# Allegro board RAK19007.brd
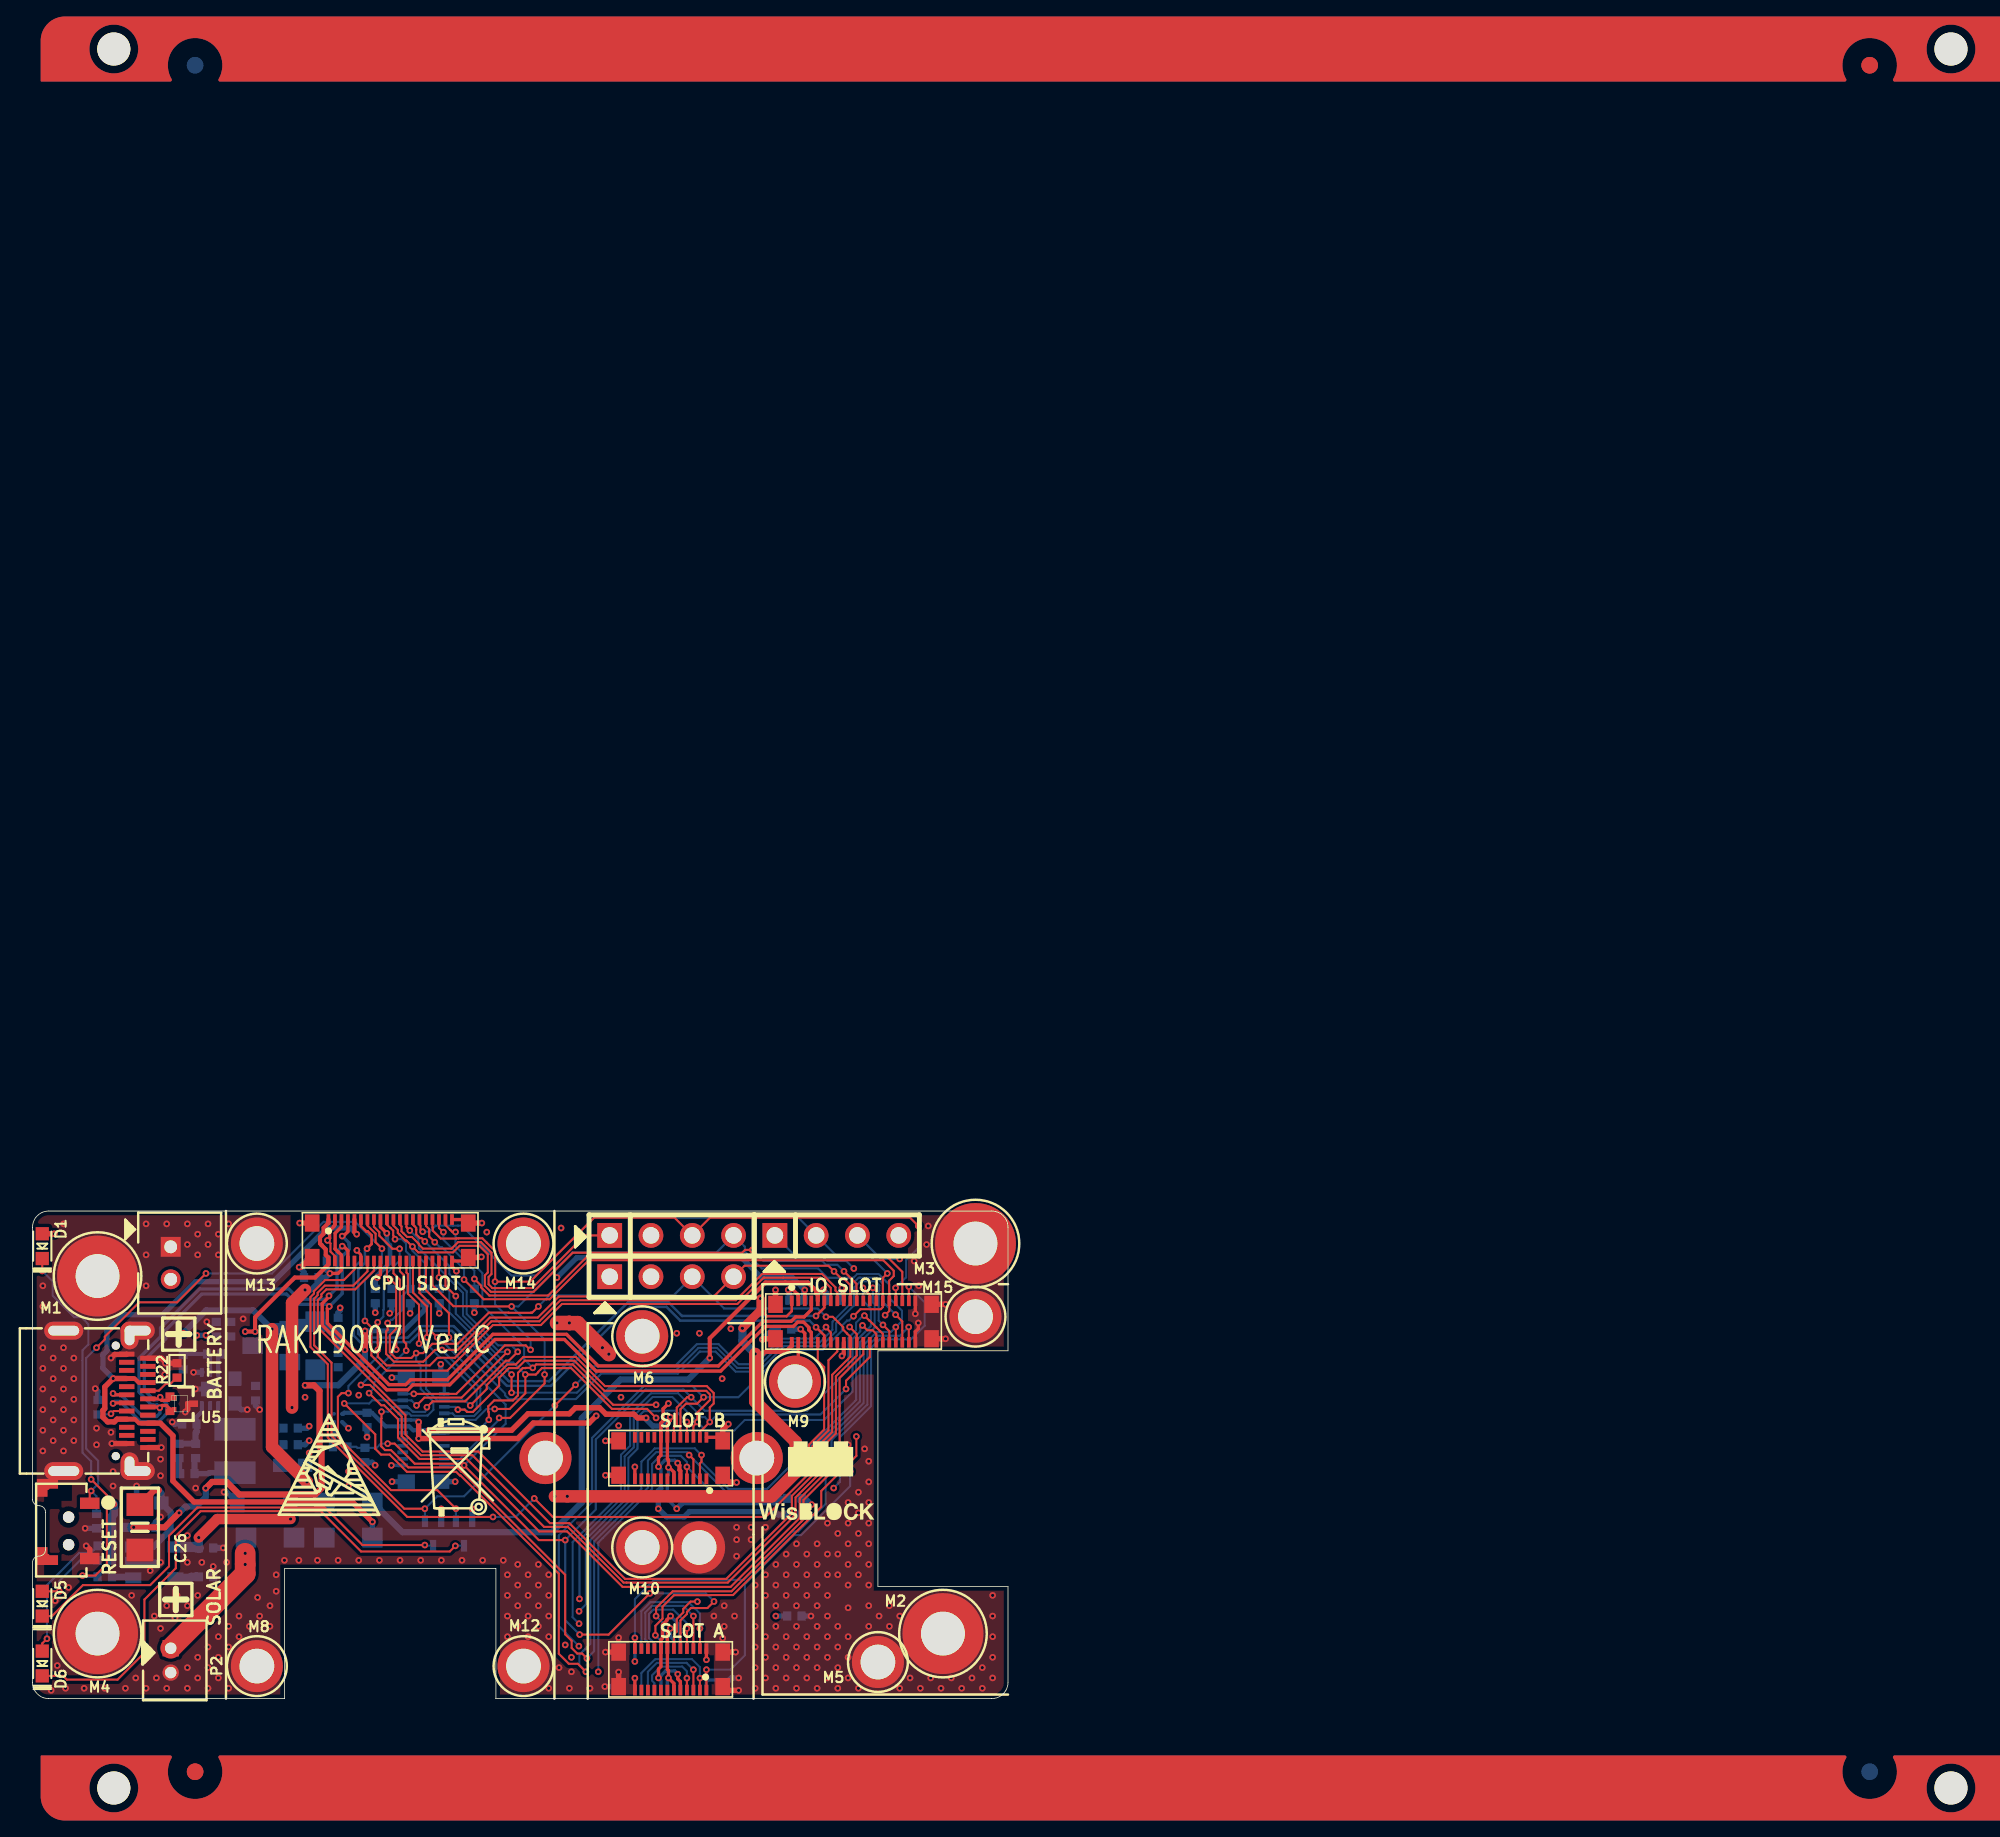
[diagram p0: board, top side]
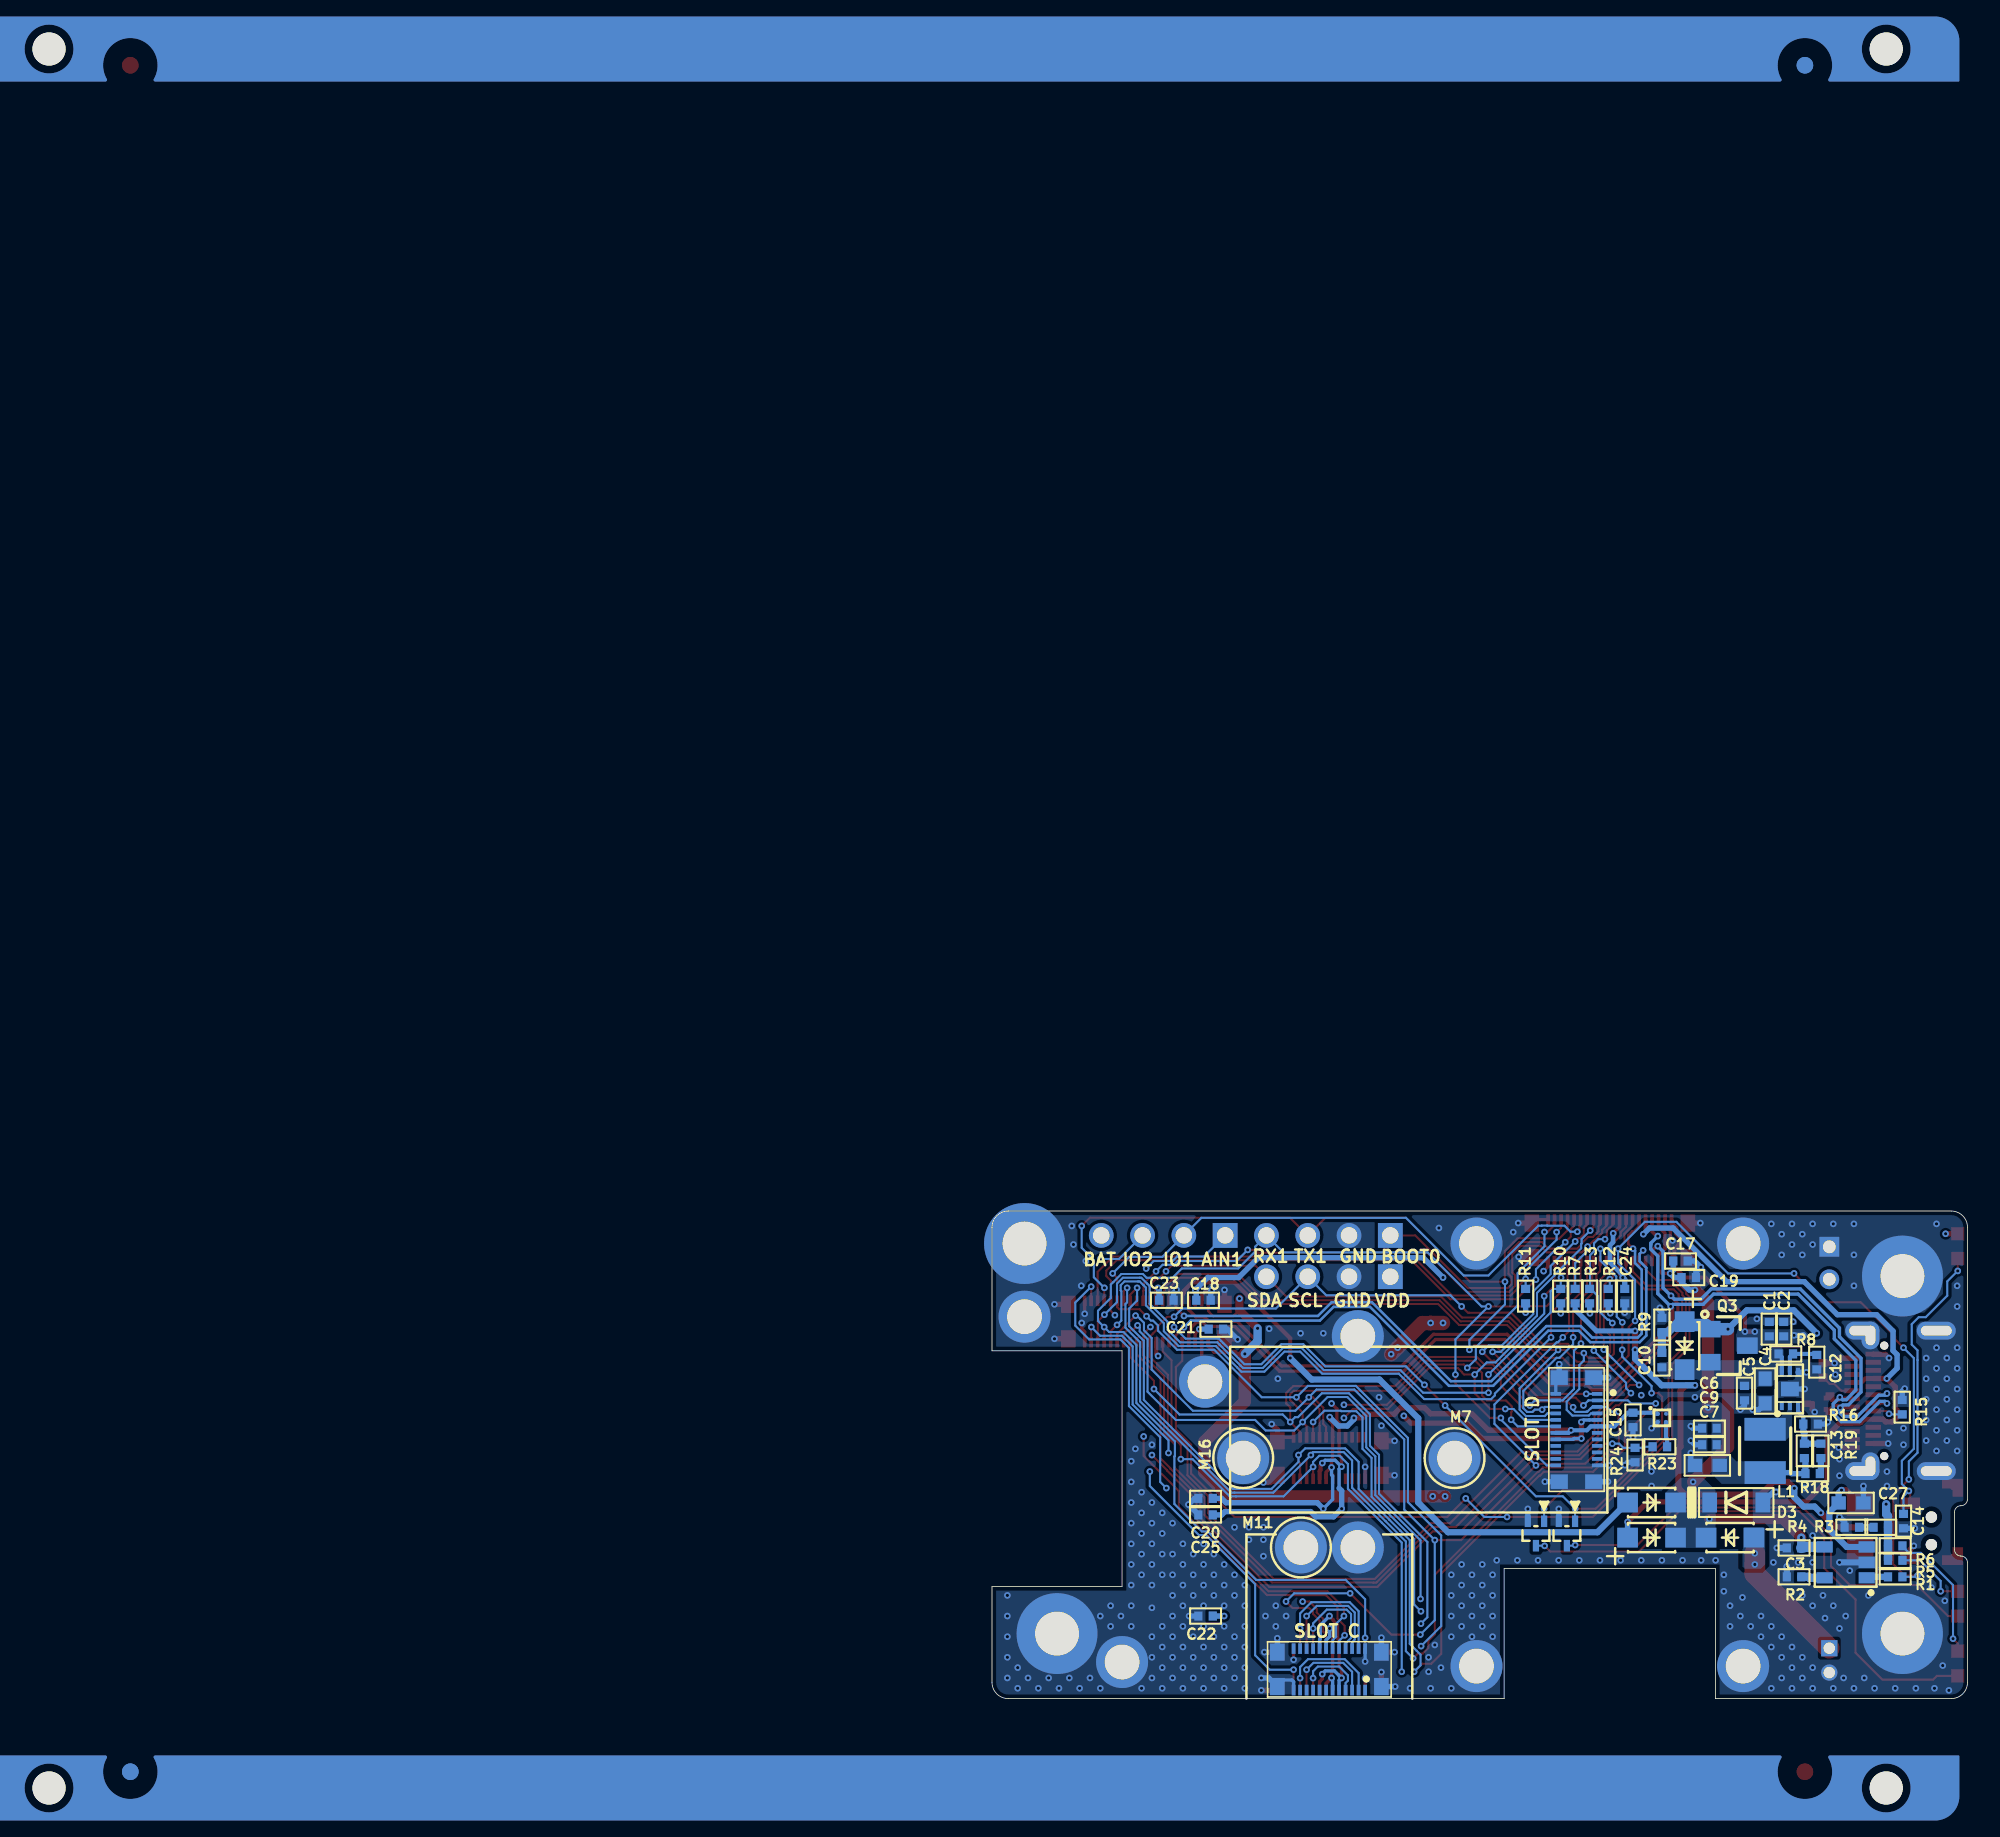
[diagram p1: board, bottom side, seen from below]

Outline 60 x 30 mm; copper layers: TOP, GND, POWER, BOTTOM. Coordinates in mm from the lower left corner of the outline.
Outline path: 0,29 0,12.27 arc(0.12,11.99) 0.4,11.87 arc(0.68,11.75) 0.8,11.47 0.8,9.17 arc(0.68,8.89) 0.4,8.77 arc(0.12,8.65) 0,8.37 0,1 arc(0.29,0.29) 1,0 15.5,0 15.5,8 28.5,8 28.5,0 59,0 arc(59.71,0.29) 60,1 60,6.9 52,6.9 52,21.4 60,21.4 60,29 arc(59.71,29.71) 59,30 1,30 arc(0.29,29.71) 0,29

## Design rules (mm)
constraint set DEFAULT: min track width 0.127
net group DIFFPAIR0: nets RXD0 TXD0
net group DIFFPAIR2: nets USB+ USB-
net group POWER: nets 3V3_S VBUS
net group DEFAULT: nets ADC_VBAT AIN0 AIN1 BOOT0 I2C1_SCL I2C1_SDA I2C2_SCL I2C2_SDA IO1 IO2 IO3 IO4 IO5 IO6 IO8 LED1 LED2 N577502 N581567 N582068 N712650 N5338470 N5774440 N5815470 RESET RXD1 SPI_CLK SPI_CS SPI_MISO SPI_MOSI SW1 TXD1

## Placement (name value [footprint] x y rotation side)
C1  10uF  [SC0402]  12.19 22.73 270 bottom
C2  100nF  [SC0402]  11.3 22.73 270 bottom
C3  1uF  [SC0402]  10.67 9.27 180 bottom
C4  22uF  [SC0603]  12.45 18.92 90 bottom
C5  100nF  [SC0402]  13.72 18.8 90 bottom
C6  10pF  [SC0402]  15.88 16.64 180 bottom
C7  22uF  [SC0603]  16 14.35 180 bottom
C9  100nF  [SC0402]  15.88 15.62 180 bottom
C10  100nF  [SC0402]  18.8 20.83 270 bottom
C12  100nF  [SC0402]  9.27 20.7 90 bottom
C13  22pF  [SC0402]  10.03 15.24 270 bottom
C14  100nF  [SC0402]  3.94 10.92 90 bottom
C15  100nF  [SC0402]  20.57 17.14 90 bottom
C17  10uF  [SC0402]  17.65 26.92 0 bottom
C18  10pF  [SC0402]  46.99 24.51 0 bottom
C19  100nF  [SC0402]  17.14 25.91 0 bottom
C20  10uF  [SC0402]  46.86 12.32 180 bottom
C21  10pF  [SC0402]  46.23 22.73 0 bottom
C22  100nF  [SC0402]  46.86 5.08 180 bottom
C23  10uF  [SC0402]  49.28 24.51 0 bottom
C24  10pF  [SC0402]  21.08 24.77 90 bottom
C25  100nF  [SC0402]  46.86 11.3 180 bottom
C26  100uF  [SC1206]  6.6 10.54 90 top
C27  22uF/NC  [SC0603]  7.16 12.04 0 bottom
D1  RED  [SD0603-LED-B]  0.6 27.84 270 top
D2  MBR140SFT1G  [MBR140SF]  19.43 9.91 180 bottom
D3  LBZT52B5V6T1G  [SOD-123]  14.22 12.06 180 bottom
D4  MBR140SFT1G  [MBR140SF]  14.61 9.91 0 bottom
D5  GREEN  [SD0603-LED-B]  0.6 5.84 270 top
D6  BLUE  [SD0603-LED-B]  0.6 2.16 270 top
D7  MBR140SFT1G  [MBR140SF]  19.43 12.06 180 bottom
D8  MBR140SFT1G  [MBR140SF]  17.4 21.72 270 bottom
J1  Type-C  [USB-C-04-24P]  5.12 14.92 270 top
J3  12VDC  [TSW4-RG_1]  2.22 10.32 270 top
J4  BTB24_F  [BTB24_2X20_4MM_F]  39.25 1.8 270 top
J5  BTB40_F  [BTB40_2X20_4MM_F]  22 28.2 90 top
J6  BTB24_F  [BTB24_2X20_4MM_F]  39.25 14.8 270 top
J7  BTB40_F  [BTB40_2X20_4MM_F]  50.5 23.2 90 top
J8  BTB24_F  [BTB24_2X20_4MM_F]  39.25 1.8 270 bottom
J9  BTB24_F  [BTB24_2X20_4MM_F]  24.05 16.55 180 bottom
J10  NC  [PH254-115-04]  39.31 28.5 90 top
J11  NC  [PH254-115-04]  49.47 28.5 90 top
J12  NC  [PH254-115-04]  39.31 25.96 90 top
L1  4.7uH  [SL1008]  12.45 15.24 270 bottom
M1  NC  [PH106-196]  4 26 0 top
M2  NC  [PH106-196]  56 4 0 top
M3  NC  [PH106-196]  58 28 0 top
M4  NC  [PH106-196]  4 4 0 top
M5  DNP  [PH84-126]  52 2.25 0 top
M6  DNP  [PH84-126]  37.5 22.3 0 top
M7  DNP  [PH84-126]  31.55 14.8 180 bottom
M8  DNP  [PH84-126]  13.8 2 0 top
M9  DNP  [PH84-126]  46.9 19.5 0 top
M10  DNP  [PH84-126]  37.5 9.3 0 top
M11  DNP  [PH84-126]  41 9.3 180 bottom
M12  DNP  [PH84-126]  30.2 2 0 top
M13  DNP  [PH84-126]  13.8 28 0 top
M14  DNP  [PH84-126]  30.2 28 0 top
M15  DNP  [PH84-126]  58 23.5 0 top
M16  DNP  [PH84-126]  44.55 14.8 180 bottom
NOREF  -  []  8.89 18.8 0 top
NOREF#2  -  []  28.7 14.35 0 top
NOREF#3  -  [unnamed#2]  0 -3 0 top
NOREF#4  -  [unnamed#2]  123 99 180 top
NOREF#5  -  []  158.12 -65.91 0 top
NOREF#6  -  []  47.75 13.21 0 top
NOREF#7  -  [unnamed#2]  123 -3 180 bottom
NOREF#8  -  [unnamed#2]  0 99 0 bottom
P1  BATT_CONN  [PH2MM_2A]  8.5 26.8 0 top
P2  Solar, Wireless charger and Wind Power input connector  [PH150-2P]  8.5 2.35 0 top
Q1  DTC043ZEBTL  [SOT-416]  24.64 10.16 0 bottom
Q2  DTC043ZEBTL  [SOT-416]  26.54 10.16 0 bottom
Q3  NCE40P05Y  [SOT23]  14.68 21.72 270 bottom
R1  1K  [SR0402]  4.45 7.49 0 bottom
R2  2.7K  [SR0402]  10.67 7.49 0 bottom
R3  1M  [SR0402]  5.33 10.54 0 bottom
R4  1.5M  [SR0402]  7.11 10.54 0 bottom
R5  4.7K  [SR0402]  4.45 8.51 0 bottom
R6  4.7K  [SR0402]  4.45 9.4 0 bottom
R7  0  [SR0402]  24.13 24.77 90 bottom
R8  4.7K  [SR0402]  11.18 21.21 180 bottom
R9  4.7K  [SR0402]  18.8 22.99 270 bottom
R10  4.7K  [SR0402]  25.02 24.77 270 bottom
R11  4.7K  [SR0402]  27.18 24.77 270 bottom
R12  4.7K  [SR0402]  22.1 24.77 270 bottom
R13  4.7K  [SR0402]  23.24 24.77 270 bottom
R15  4.7K  [SR0402]  4.01 17.93 90 bottom
R16  1M  [SR0402]  9.65 16.89 0 bottom
R18  1.5M  [SR0402]  9.53 13.84 0 bottom
R19  800K  [SR0402]  9.02 15.24 270 bottom
R22  4.7K  [SR0402]  8.89 20.19 90 top
R23  10K  [SR0402]  18.92 15.49 180 bottom
R24  100k/NC  [SR0402]  20.45 14.99 270 bottom
U2  TP4054  [SOT-23-5]  6.2 8.38 90 bottom
U3  SGM6036-ADJ  [UTDFN-1_5X2-6L]  10.92 19.05 90 bottom
U4  TPD2EUSB30DRTR/NC  [3PSOT41X33F]  8.7 18.49 270 top
U5  PPJE5V0U8TB-AU  [SOT-523]  9.18 18.14 270 top
U6  SGM2578AADYG/TR  [DSBGA_0_9X0_9MM]  18.8 17.27 180 bottom

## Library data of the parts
C1-C7 C9 C10 C12-C15 C17-C27 = CAPACITOR NP
D1 D5 D6 = LED
D2 D4 D7 D8 = DIODE_SCHOTTKY
D3 = DIODE_ZENER_INV
J1 = CONN_USB3_0
J3 = BUTTON_1
J4 J6 J8 J9 = BTB24_2X12_0
J5 J7 = BTB40_2x20_4mm
J10-J12 = HEADER1X4: User Part Number: PH254-115-04
L1 = INDUCTOR _POWER
M1-M16 = HOLE
P1 = HEADER2: User Part Number: NC
P2 = HEADER2_150
Q1 Q2 = TRIODE_NPN_RES
Q3 = MOSFET_P_DIODE_3P
R1-R13 R15 R16 R18 R19 R22-R24 = RESISTOR
U2 = TP4054
U3 = SGM6036-ADJ
U4 = TPD2EUSB30DRTR: User Part Number: PART
U5 = TVS_3PIN
U6 = TPS22908

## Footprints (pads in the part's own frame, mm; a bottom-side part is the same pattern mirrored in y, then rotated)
3PSOT41X33F
  rect 0.3x0.3 smd: 1(0,0) 2(0.7,0) 3(0.35,0.85)
BTB24_2X20_4MM_F
  rect 0.65x0.23 smd: 1(1.275,2.2) 2(-1.275,2.2) 3(1.275,1.8) 4(-1.275,1.8) 5(1.275,1.4) 6(-1.275,1.4) 7(1.275,1) 8(-1.275,1) 9(1.275,0.6) 10(-1.275,0.6) 11(1.275,0.2) 12(-1.275,0.2) 13(1.275,-0.2) 14(-1.275,-0.2) 15(1.275,-0.6) 16(-1.275,-0.6) 17(1.275,-1) 18(-1.275,-1) 19(1.275,-1.4) 20(-1.275,-1.4) 21(1.275,-1.8) 22(-1.275,-1.8) 23(1.275,-2.2) 24(-1.275,-2.2)
  rect 1.06x0.9 smd: F1(-1.06,3.2) F2(1.06,3.2) F3(-1.06,-3.2) F4(1.06,-3.2)
BTB40_2X20_4MM_F
  rect 0.65x0.23 smd: 1(1.275,3.8) 2(-1.275,3.8) 3(1.275,3.4) 4(-1.275,3.4) 5(1.275,3) 6(-1.275,3) 7(1.275,2.6) 8(-1.275,2.6) 9(1.275,2.2) 10(-1.275,2.2) 11(1.275,1.8) 12(-1.275,1.8) 13(1.275,1.4) 14(-1.275,1.4) 15(1.275,1) 16(-1.275,1) 17(1.275,0.6) 18(-1.275,0.6) 19(1.275,0.2) 20(-1.275,0.2) 21(1.275,-0.2) 22(-1.275,-0.2) 23(1.275,-0.6) 24(-1.275,-0.6) 25(1.275,-1) 26(-1.275,-1) 27(1.275,-1.4) 28(-1.275,-1.4) 29(1.275,-1.8) 30(-1.275,-1.8) 31(1.275,-2.2) 32(-1.275,-2.2) 33(1.275,-2.6) 34(-1.275,-2.6) 35(1.275,-3) 36(-1.275,-3) 37(1.275,-3.4) 38(-1.275,-3.4) 39(1.275,-3.8) 40(-1.275,-3.8)
  rect 1.06x0.9 smd: F1(-1.06,4.8) F2(1.06,4.8) F3(-1.06,-4.8) F4(1.06,-4.8)
DSBGA_0_9X0_9MM
  round 0.23 smd: A1(-0.25,0.25) A2(0.25,0.25) B1(-0.25,-0.25) B2(0.25,-0.25)
MBR140SF
  rect 1.27x1.219 smd: 1(-1.475,0) 2(1.475,0)
PH2MM_2A
  rect 1.219x1.219 hole 0.787: 1(0,1)
  round 1.219 hole 0.787: 2(0,-1)
PH84-126
  round 3.2 hole 2.134: 1(0,0)
PH106-196
  round 4.978 hole 2.692: 1(0,0)
PH150-2P
  rect 1x1 hole 0.7: 1(0,0.75)
  round 1 hole 0.7: 2(0,-0.75)
PH254-115-04
  rect 1.524x1.524 hole 1.016: 1(0,3.81)
  round 1.524 hole 1.016: 2(0,1.27) 3(0,-1.27) 4(0,-3.81)
SC0402
  rect 0.508x0.559 smd: 1(-0.445,0) 2(0.445,0)
SC0603
  rect 0.889x0.813 smd: 1(-0.762,0) 2(0.762,0)
SC1206
  rect 1.397x1.651 smd: 1(-1.397,0) 2(1.397,0)
SD0603-LED-B
  rect 0.813x0.813 smd: 1(-0.762,0) 2(0.762,0)
SL1008
  rect 1.397x2.54 smd: 1(-1.333,0) 2(1.333,0)
SOD-123
  rect 0.91x1.22 smd: 1(-1.635,0) 2(1.635,0)
SOT23
  rect 1.016x1.27 smd: 1(-1.016,-1.143) 2(1.016,-1.143) 3(0,1.143)
SOT-23-5
  rect 0.69x0.99 smd: 1(-0.95,0)
  rect 0.69x1 smd: 2(0,0) 3(0.95,0) 4(0.95,2.59) 5(-0.95,2.59)
SOT-416
  rect 0.381x0.711 smd: 1(-0.5,-0.75) 2(0.5,-0.75) 3(0,0.75)
SOT-523
  rect 0.4x0.55 smd: 1(-0.5,-0.725) 2(0.5,-0.725) 3(0,0.725)
SR0402
  rect 0.508x0.559 smd: 1(-0.445,0) 2(0.445,0)
TSW4-RG_1
  round 0.7 hole 0.7 unplated: (-0.85,0) (0.85,0)
  rect 0.7x1.2 smd: 1(-1.7,1.3) 2(1.7,1.3)
  custom 0.275x0.275 smd: 3(-2.65,-1.3) 4(1.55,-1.3)
unnamed#2
  round 2.032 hole 2.032 unplated: (5,-2.5)
  round 1.016 smd: (10,-1.5) (10,-1.5)
USB-C-04-24P
  round 0.5 hole 0.5 unplated: (-6.8,0) (0,0)
  oval 1.1x2.4 hole 0.6x1.9: 1(-7.72,-3.201) 2(0.92,-3.201)
  oval 1.1x2.1 hole 0.6x1.6: 3(-7.72,1.349) 4(0.92,1.349)
  oval 1.7x1.1 hole 1.2x0.6: 7(-7.42,0.848) 8(0.62,0.848)
  rect 0.3x0.95 smd: A1(-6.025,1.975) A2(-5.525,1.975) A3(-5.025,1.975) A4(-4.525,1.975) A5(-4.025,1.975) A6(-3.525,1.975) A7(-3.025,1.975) A8(-2.525,1.975) A9(-2.025,1.975) A10(-1.525,1.975) A11(-1.025,1.975) A12(-0.525,1.975) B1(-0.775,0.675) B2(-1.275,0.675) B3(-1.775,0.675) B4(-2.275,0.675) B5(-2.775,0.675) B6(-3.275,0.675) B7(-3.775,0.675) B8(-4.275,0.675) B9(-4.775,0.675) B10(-5.275,0.675) B11(-5.775,0.675) B12(-6.275,0.675)
UTDFN-1_5X2-6L
  rect 0.55x0.25 smd: 1(-1.025,0.5) 2(-1.025,0) 3(-1.025,-0.5) 4(1.025,-0.5) 5(1.025,0) 6(1.025,0.5)
  rect 0.9x1.1 smd: 7(0,0)

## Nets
3V3: C6.2 C7.2 C9.2 C13.2 C17.2 C18.2 C19.2 J5.5 J5.6 J7.5 L1.2 R18.2 U6.A2
3V3_S: C15.2 C20.2 C21.2 C22.2 J4.11 J4.14 J6.11 J6.14 J7.6 J8.11 J8.14 J9.11 J9.14 U6.A1(VOUT)
GND: C1.1(POS) C2.1(POS) C3.1(POS) C4.1(POS) C5.1(POS) C6.1(POS) C7.1(POS) C9.1(POS) C12.1(POS) C14.1(POS) C15.1(POS) C17.1(POS) C18.1(POS) C19.1(POS) C20.1(POS) C21.1(POS) C22.1(POS) C23.1(POS) C24.1(POS) C25.1(POS) C26.1(POS) C27.1(POS) D3.2 J1.1 J1.2 J1.3 J1.4 J1.7 J1.8 J1.A1 J1.A12 J1.B1 J1.B12 J3.2(P2) J4.2 J4.23 J4.F1 J4.F2 J4.F3 J4.F4 J5.3 J5.4 J5.39 J5.40 J5.F1 J5.F2 J5.F3 J5.F4 J6.2 J6.23 J6.F1 J6.F2 J6.F3 J6.F4 J7.3 J7.4 J7.39 J7.40 J7.F1 J7.F2 J7.F3 J7.F4 J8.2 J8.23 J8.F1 J8.F2 J8.F3 J8.F4 J9.2 J9.23 J9.F1 J9.F2 J9.F3 J9.F4 J10.2 J12.2 M1.1 M2.1 M3.1 M4.1 M5.1 M6.1 M7.1 M8.1 M9.1 M10.1 M11.1 M12.1 M13.1 M14.1 M15.1 M16.1 P1.1 P2.2 Q1.2(E) Q2.2(E) R2.2 R4.2 R9.1 R15.2 R16.1 R22.2 R24.2 U2.2 U3.4 U3.7 U4.3(GND) U5.3 U6.B1
VBAT: C1.2 C2.2 C26.2 C27.2 J5.1 J5.2 J7.1 J7.2 J11.4 P1.2 Q3.3 R3.1 R5.2 R6.2 U2.3
VBUS: D2.1 J1.A4 J1.A9 J1.B4(VBUS3) J1.B9 J5.9
VBUS_D: C3.2 C10.1(POS) D1.1 D2.2(CATHODE) D3.1(CATHODE) D4.2(CATHODE) D7.2(CATHODE) D8.1 Q3.1 R9.2 U2.4(VCC)
VCC: C4.2 C5.2 C10.2 D8.2(CATHODE) Q3.2(S) R8.1 U3.6(VIN)
VCC_IN: D7.1 J7.9
VDD: C23.2 C24.2 C25.2 J4.9 J4.16(VDD2) J5.17 J5.18(VDD_2) J6.9 J6.16(VDD2) J7.17 J7.18(VDD_2) J8.9 J8.16(VDD2) J9.9 J9.16(VDD2) J12.1 R10.2 R11.2 R12.2 R13.2
ADC_VBAT: R3.2 R4.1 R7.1
AIN0: J5.21 J7.21 R7.2
AIN1: J5.22 J7.22 J11.1
BOOT0: J5.23 J10.1
EN: C12.2 R8.2 U3.5
GREEN_POWER: D4.1 P2.1
I2C1_SCL: J4.7 J5.20 J6.7 J7.20 J8.7 J9.7 J12.3 R12.1
I2C1_SDA: J4.8 J5.19 J6.8 J7.19 J8.8 J9.8 J12.4 R13.1
I2C2_SCL: J5.36 J7.36 R10.1
I2C2_SDA: J5.35 J7.35 R11.1
IO1: J4.12 J5.29 J6.10 J7.29 J11.2
IO2: J4.10 J5.30 J6.12 J7.30 J11.3 R23.1 R24.1
IO3: J5.31 J7.31 J8.12
IO4: J5.32 J7.32 J8.10
IO5: J5.37 J7.37 J9.12
IO6: J5.38 J7.38 J9.10
IO7: J5.24 J7.24
IO8: J5.16 J7.16
LED1: J5.14 J7.14 Q1.1
LED2: J5.15 J7.15 Q2.1
RESET: C14.2 J3.1 J5.13 J7.13
RXD0: J5.12 J7.12
RXD1: J4.24 J5.34 J7.34 J9.24 J10.4
SPI_CLK: J4.4 J5.26 J6.4 J7.26 J8.4 J9.4
SPI_CS: J4.3 J5.25 J6.3 J7.25 J8.3 J9.3
SPI_MISO: J4.5 J5.27 J6.5 J7.27 J8.5 J9.5
SPI_MOSI: J4.6 J5.28 J6.6 J7.28 J8.6 J9.6
SW1: J5.10 J7.10
TXD0: J5.11 J7.11
TXD1: J4.1 J5.33 J7.33 J9.1 J10.3
USB+: J1.A6 J1.B6 J5.7 J7.7 U4.1 U5.1
USB-: J1.A7 J1.B7 J5.8 J7.8 U4.2 U5.2
N577502: D5.2(CATHODE) Q1.3
N581567: R2.1 U2.5
N582068: D1.2(CATHODE) R1.1
N712650: D6.2(CATHODE) Q2.3
N724860: L1.1 U3.2
N784297: C13.1(POS) R16.2 R19.1 U3.3
N789136: R18.1 R19.2
N816306: J1.A5 R22.1
N816310: J1.B5 R15.1
N918116: R23.2 U6.B2
N5338470: D6.1 R6.1
N5774440: D5.1 R5.1
N5815470: R1.2 U2.1

Pads without a net: J1 A2 A3 A8 A10 A11 B2 B3 B8 B10 B11; J3 3 4; J4 13 15 17 18 19 20 21 22; J6 1 13 15 17 18 19 20 21 22 24; J7 23; J8 1 13 15 17 18 19 20 21 22 24; J9 13 15 17 18 19 20 21 22; U3 1

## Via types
v1: diameter 0.41, hole 0.2, TOP to BOTTOM, 542 vias

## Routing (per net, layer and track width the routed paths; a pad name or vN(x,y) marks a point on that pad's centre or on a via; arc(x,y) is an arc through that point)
3V3: length 50.9
  TOP w0.203: v1(18.29,26.16) 18.79,26.16 19,26.37 J5.6 19,27.29 18.81,27.48 18.8,27.48 18.62,27.66 18.62,27.68 18.61,27.69 18.61,28.64 19,29.02 J5.5 ; J7.5 47.5,25.14 v1(47.5,25.15)
  TOP w0.762: v1(16.76,25.15) 15.96,24.34 v1(15.96,17.91)
  POWER w0.635: v1(32.26,25.91) 29.11,25.91 28.49,26.53 26.77,26.53 26.32,26.98 20.27,26.98 19.83,26.54 18.67,26.54 v1(18.29,26.16)
  BOTTOM w0.33: C18.2 47.43,25.08 v1(47.5,25.15) 46.74,25.91 44.83,25.91 43.61,27.13 33.48,27.13 v1(32.26,25.91) ; C17.2 18.1,26.35 v1(18.29,26.16) 18.03,25.91 C19.2 17.59,25.62 17.12,25.15 v1(16.76,25.15) ; R18.2 10.82,13.84 10.88,13.91 L1.2
  BOTTOM w0.381: R18.2 9.97,14.73 C13.2
3V3_S: length 79.9
  TOP w0.203: v1(47.24,22.73) 47.5,22.48 J7.6 ; v1(39.23,4.32) 39.23,4.31 39.05,4.13 J4.14 39.05,1.79 39.12,1.73 v1(39.12,1.27) 39.45,0.94 J4.11 ; J6.11 39.45,13.94 39.16,14.22 v1(39.12,14.22) 39.12,14.68 39.05,14.75 J6.14 39.05,16.92 39.23,17.1 v1(39.23,17.32)
  TOP w0.33: v1(24.38,16.51) 29.46,16.51 30.48,17.53 33.02,17.53 33.39,17.9 34.88,17.9 35.28,17.5 36.99,17.5 37.22,17.27 v1(37.74,17.27)
  POWER w0.203: v1(39.23,4.32) 39.88,4.97 39.88,5.72 40.64,6.48 42.93,6.48 44.32,5.08 v1(45.72,5.08)
  POWER w0.381: v1(47.24,22.73) 42.2,17.69 39.6,17.69 v1(39.23,17.32)
  POWER w0.508: 36.51,5.52 37.56,4.48 38.55,4.48 38.72,4.32 v1(39.23,4.32)
  POWER w0.635: v1(39.62,11.68) 38.73,12.57 35.94,12.57 34.16,10.79 34.16,7.87 36.51,5.52
  BOTTOM w0.203: v1(39.12,1.27) 39.05,1.2 J8.11 ; v1(39.12,14.22) 39.12,13.76 39.05,13.7 39.05,12.26 v1(39.62,11.68) ; v1(39.23,4.32) 39.23,3.82 39.45,3.6 J8.14
  BOTTOM w0.254: J9.14 24.54,16.35 v1(24.38,16.51) 23.41,16.51 23.17,16.75 J9.11 21.72,16.75 20.88,17.59 C15.2 19.18,17.59 19.11,17.52 U6.A1
  BOTTOM w0.33: v1(39.23,17.32) 38.69,16.77 38.15,16.77 37.74,17.18 v1(37.74,17.27) ; v1(39.62,11.68) 39.99,12.05 45.61,12.05 45.87,12.32 C20.2 ; C22.2 v1(45.72,5.08) ; C21.2 v1(47.24,22.73)
GND: length 71.7
  TOP w0.127: v1(18.14,28.19) 18.33,28.01 18.33,27.51 18.6,27.23 J5.4
  TOP w0.203: v1(26.07,26.3) 25.8,26.58 J5.40 26.58,26.93 J5.F3 ; v1(54.48,23.11) 54.48,22.75 54.3,22.57 J7.40 ; v1(46.48,25.15) 46.79,25.15 47.04,24.89 47.04,24.88 47.1,24.83 J7.3 ; J6.2 42.24,16.08 J6.F1 ; v1(18.14,28.19) 18.27,28.32 18.27,28.79 18.54,29.06 18.54,29.08 18.6,29.14 J5.3 ; M9.1 47.1,19.7 J7.4 ; J6.23 v1(37.05,14.26) ; J5.39 26.58,29.48 J5.F4 ; J7.39 v1(54.3,23.68) ; J4.2 v1(41.45,2.39) ; J4.23 v1(37.05,1.26)
  TOP w0.33: J7.F3 v1(56.16,22.14) ; J1.B1 v1(4.88,15.69) ; v1(27.61,27.18) 27.43,27.18 27.39,27.14 J5.F3 ; J6.F3 v1(35.24,15.86) ; v1(42.8,16.89) 42.45,16.54 J6.F1 ; v1(43.43,0.51) 42.68,0.51 J4.F2 ; v1(44.89,22.1) 44.96,22.1 45,22.14 J7.F1 ; J4.F1 v1(43.25,2.86) ; J1.A12 v1(7.92,15.44) ; v1(9.4,17.63) 9.4,17.65 9.55,17.8 U4.3 9.9,18.14 U5.3 ; v1(4.83,20.95) 5.05,21.18 5.78,21.18 J1.B12 ; R22.2 v1(8.18,20.64) 8.18,20.7 7.93,20.94 J1.A1 ; J6.F4 v1(35.24,13.74) ; J6.F2 42.89,13.3 v1(43.31,13.3) ; J4.F3 v1(35.24,2.86) ; v1(3.3,9.4) 3.52,9.18 J3.2 ; J5.F2 v1(16.43,29.26) ; J4.F4 v1(36.05,1.63) ; J7.F2 v1(45.7,25.15) ; v1(16.4,26.54) 16.51,26.54 17.11,27.14 J5.F1 ; J7.F4 v1(56.16,24.26) ; v1(27.64,29.26) J5.F4
  BOTTOM w0.203: J9.23 v1(22.07,14.35) ; J9.2 25.32,19.53 J9.F1 ; J4.F2 42.05,1.14 41.55,1.14 41.45,1.04 J8.23 ; J8.2 v1(37.05,2.29)
  BOTTOM w0.254: U6.B1 v1(19.43,16.64)
  BOTTOM w0.33: D3.2 11.95,12.71 v1(11.78,12.71) ; J9.F3 v1(26,13.35) ; v1(44.89,22.1) 45.53,22.73 C21.1 ; C24.1 v1(21.08,23.75) ; v1(13.21,17.78) 12.83,17.78 C4.1 ; v1(17.02,15.88) 16.76,15.62 C9.1 ; C23.1 48.83,24.96 48.65,25.13 v1(48.65,25.16) ; v1(18.92,24.04) 18.92,23.88 18.8,23.75 R9.1 ; J9.F2 v1(22.1,19.75) ; C14.1 v1(3.24,10.48) ; R16.1 8.72,16.89 v1(8.6,17.02) ; R15.2 4.01,18.92 v1(3.86,19.08) ; C5.1 13.72,18.03 v1(13.97,17.78) ; R24.2 20.89,14.54 v1(21.07,14.36) ; U3.7 v1(10.01,19.05) ; Q1.2 v1(25.14,11.67) ; J9.F4 v1(22.11,13.35) ; v1(17.02,16.76) 16.89,16.64 C6.1 ; J4.F1 v1(42.45,3.72) ; Q2.2 v1(27.04,11.67) ; v1(43.43,1.27) 42.98,1.27 J4.F2 ; C22.1 v1(47.88,5.08) ; C19.1 16.7,26.24 v1(16.4,26.54) 16.78,26.92 C17.1 ; v1(7.87,11.18) 7.56,10.86 R4.2 ; J9.F1 v1(25.11,20.57) ; J4.F3 v1(36.05,3.75) ; C18.1 46.55,25.08 46.48,25.15 v1(46.48,25.15) ; C25.1 47.31,11.33 v1(47.92,11.94) 47.54,12.32 C20.1 ; v1(17.02,15.11) 17.02,14.61 C7.1 ; J4.F4 v1(35.2,0.74) ; U3.4 v1(9.91,20.07) ; C15.1 v1(20.57,16.09) ; C27.1 v1(6.4,13.08)
  BOTTOM w0.381: R2.2 v1(11.11,8.13) ; U2.2 v1(7.87,8.38) ; C3.1 v1(11.72,9.27)
  vias: v1(0.64,25.4) v1(0.64,24.13) v1(0.64,21.59) v1(0.64,20.32) v1(0.64,19.05) v1(0.64,17.78) v1(0.64,16.51) v1(0.64,15.24) v1(1.14,0.51) v1(1.27,20.95) v1(1.27,19.68) v1(1.27,18.41) v1(1.27,17.14) v1(1.27,15.88) v1(1.4,6.02) v1(1.52,2.03) v1(1.91,29.21) v1(1.91,21.59) v1(1.91,20.32) v1(1.91,19.05) v1(1.91,17.78) v1(1.91,16.51) v1(1.91,15.24) v1(2.03,0.64) v1(2.22,6.84) v1(2.54,20.95) v1(2.54,19.68) v1(2.54,18.41) v1(2.54,17.14) v1(2.54,15.88) v1(3.17,0.64) v1(3.94,16.64) v1(3.94,15.62) v1(4.45,0.64) v1(4.83,16.38) v1(4.95,13.97) v1(4.95,13.08) v1(5.71,0.64) v1(6.1,6.35) v1(6.35,1.27) v1(6.99,29.21) v1(6.99,27.3) v1(6.99,25.4) v1(6.99,0.64) v1(7.24,7.87) v1(7.49,5.08) v1(7.62,1.27) v1(7.87,14.73) v1(7.87,13.72) v1(7.87,4.32) v1(8.13,19.94) v1(8.26,29.21) v1(8.26,5.71) v1(8.26,0.64) v1(8.76,4.95) v1(8.89,6.35) v1(9.53,29.21) v1(9.53,27.94) v1(9.53,10.03) v1(9.53,8.38) v1(9.53,5.71) v1(9.53,1.91) v1(9.53,0.64) v1(10.03,12.95) v1(10.16,28.57) v1(10.16,27.3) v1(10.16,6.35) v1(10.16,2.54) v1(10.16,1.27) v1(10.41,8.38) v1(10.72,23.19) v1(10.79,29.21) v1(10.79,27.94) v1(10.79,3.17) v1(10.79,1.91) v1(10.79,0.64) v1(11.43,28.57) v1(11.43,27.3) v1(11.43,3.81) v1(11.43,2.54) v1(11.43,1.27) v1(11.94,8.38) v1(12.06,29.21) v1(12.06,4.45) v1(12.06,3.17) v1(12.06,0.64) v1(12.7,5.08) v1(12.7,3.81) v1(12.95,23.37) v1(13.34,4.45) v1(13.84,6.22) v1(13.97,5.08) v1(14.61,5.71) v1(14.61,4.45) v1(14.99,7.62) v1(14.99,6.6) v1(15.49,8.51) v1(16.38,8.51) v1(16.76,18.54) v1(17.53,8.51) v1(18.8,8.51) v1(19.44,13.98) v1(19.43,13.08) v1(20.07,18.67) v1(20.07,8.51) v1(21.34,8.51) v1(22.61,8.51) v1(23.88,8.51) v1(25.15,8.51) v1(26.42,8.51) v1(27.69,8.51) v1(27.94,28.7) v1(28.96,8.51) v1(29.21,7.62) v1(29.21,6.35) v1(29.21,5.08) v1(29.21,3.81) v1(29.84,8.26) v1(29.84,6.99) v1(29.84,5.71) v1(29.84,4.45) v1(30.48,7.62) v1(30.48,6.35) v1(30.48,5.08) v1(30.48,3.81) v1(31.11,8.26) v1(31.11,6.99) v1(31.11,5.71) v1(31.11,4.45) v1(31.75,7.62) v1(31.75,6.35) v1(31.75,5.08) v1(31.75,3.81) v1(31.75,0.64) v1(32.38,1.91) v1(32.51,28.96) v1(32.77,3.3) v1(33.02,0.64) v1(33.15,2.54) v1(33.15,1.65) v1(34.29,0.64) v1(36.05,16.79) v1(36.2,18.54) v1(39.62,22.48) v1(41.02,22.48) v1(41.91,5.08) v1(42.42,19.68) v1(42.55,5.71) v1(42.55,4.45) v1(42.95,22.76) v1(43.18,5.08) v1(43.31,10.54) v1(43.31,9.78) v1(43.31,8.76) v1(44.2,10.54) v1(44.2,9.78) v1(44.45,6.99) v1(44.45,5.71) v1(44.45,4.45) v1(44.45,3.17) v1(44.45,1.91) v1(44.45,0.64) v1(45.09,10.54) v1(45.09,7.62) v1(45.09,6.35) v1(45.09,3.81) v1(45.09,2.54) v1(45.09,1.27) v1(45.72,8.26) v1(45.72,6.99) v1(45.72,5.71) v1(45.72,4.45) v1(45.72,3.17) v1(45.72,1.91) v1(45.72,0.64) v1(46.35,8.89) v1(46.35,7.62) v1(46.35,6.35) v1(46.35,3.81) v1(46.35,2.54) v1(46.35,1.27) v1(46.99,9.53) v1(46.99,8.26) v1(46.99,6.99) v1(46.99,5.71) v1(46.99,4.45) v1(46.99,3.17) v1(46.99,1.91) v1(46.99,0.64) v1(47.62,8.89) v1(47.62,7.62) v1(47.62,6.35) v1(47.62,3.81) v1(47.62,2.54) v1(47.62,1.27) v1(48.26,9.53) v1(48.26,8.26) v1(48.26,6.99) v1(48.26,5.71) v1(48.26,4.45) v1(48.26,3.17) v1(48.26,1.91) v1(48.26,0.64) v1(48.9,10.79) v1(48.9,8.89) v1(48.9,7.62) v1(48.9,6.35) v1(48.9,5.08) v1(48.9,3.81) v1(48.9,2.54) v1(48.9,1.27) v1(49.53,11.43) v1(49.53,10.16) v1(49.53,8.89) v1(49.53,7.62) v1(49.53,4.45) v1(49.53,3.17) v1(49.53,1.91) v1(49.53,0.64) v1(50.16,15.62) v1(50.16,12.06) v1(50.16,10.79) v1(50.16,9.53) v1(50.16,8.26) v1(50.16,6.99) v1(50.16,5.59) v1(50.16,3.81) v1(50.16,2.54) v1(50.16,1.27) v1(50.8,12.7) v1(50.8,11.43) v1(50.8,10.16) v1(50.8,8.89) v1(50.8,7.62) v1(50.8,0.64) v1(51.18,15.37) v1(51.44,14.61) v1(51.44,13.34) v1(51.44,12.06) v1(51.44,10.79) v1(51.44,9.53) v1(51.44,8.26) v1(51.44,6.99) v1(51.44,5.71) v1(51.44,4.45) v1(52.07,5.08) v1(52.7,5.71) v1(52.7,4.45) v1(53.34,5.08) v1(53.34,0.64) v1(53.98,1.27) v1(54.23,26.92) v1(54.51,25.4) v1(54.61,0.64) v1(54.99,27.94) v1(55.1,29.08) v1(55.24,1.27) v1(55.88,0.64) v1(56.52,1.27) v1(57.15,0.64) v1(57.78,1.27) v1(58.42,1.91) v1(58.42,0.64) v1(59.05,6.35) v1(59.05,5.08) v1(59.05,3.81) v1(59.05,2.54) v1(59.05,1.27)
VBAT: length 107.9
  TOP w0.152: J7.1 46.7,23.84 46.39,23.53 45.17,23.53 44.78,23.91
  TOP w0.254: J7.2 46.7,21.72 46.32,21.34 45.06,21.34 44.93,21.21 v1(44.45,21.21) ; v1(13.08,22.58) v1(13.69,22.58) 13.69,23.47 16.13,25.91 17.38,25.91 18.2,26.72 J5.2 18.2,27.14 18.03,27.3 18.03,27.65 17.78,27.9 17.78,27.91 17.68,28 17.68,28.38 17.91,28.61 17.91,28.97 18.2,29.27 J5.1
  TOP w0.381: v1(7.75,12.83) 7.49,12.83 C26.2
  TOP w0.508: v1(44.78,24.61) 44.78,23.9 v1(43.66,22.78)
  TOP w0.762: v1(32.13,12.45) v1(32.89,12.45) 45.47,12.45 46.94,13.92 46.94,15.8 44.45,18.29 v1(44.45,21.21)
  POWER w0.254: J11.4 51.7,26.92 48.13,26.92 46.86,25.65 45.21,25.65 44.78,25.22 v1(44.78,24.61)
  POWER w0.762: v1(13.69,22.58) v1(13.08,22.58) 13.08,21.59 10.88,19.39 10.88,17.96 8.89,15.97 8.89,12.83 ; v1(5,11.96) 6.88,11.96 v1(7.75,12.83) 8.89,12.83 ; v1(32.89,12.45) v1(32.13,12.45) 29.84,10.16 24.43,10.16 24.43,10.16 23.83,10.16 23.83,10.16 11.56,10.16 8.89,12.83
  BOTTOM w0.33: v1(10.67,22.35) v1(10.11,22.35)
  BOTTOM w0.381: v1(7.75,12.83) 7.92,12.65 C27.2 8.49,11.47 8.49,10.4 7.43,9.33 U2.3
  BOTTOM w0.508: v1(44.45,21.21) 43.66,22 v1(43.66,22.78) ; v1(5,11.96) 5,11.35 4.89,11.24 R3.1 R6.2 R5.2
VBUS: length 49.2
  TOP w0.254: J1.A9 6.55,16.94 6.3,17.19 J1.B4 ; J1.B9 6.28,19.69 6.53,19.44 J1.A4 ; v1(19.94,28.57) 19.8,28.7 J5.9
  TOP w0.33: J1.B9 v1(4.96,19.69) 4.45,19.18 4.45,17.85 4.33,17.73 4.33,17.32 4.62,17.03 5.03,17.03 5.2,17.19 J1.B4 ; J1.A9 7.86,16.94 8.64,16.17 8.64,13.39 9.93,12.1 19.68,12.1 v1(20.91,10.87)
  BOTTOM w0.33: v1(19.94,28.57) 19.56,28.96 18.11,28.96 14.81,25.65 10.03,25.65 8,23.62 5.59,23.62 4.58,22.61 4.58,21.41 4.33,21.16 4.33,20.33 v1(4.96,19.69) ; D2.1 v1(20.91,10.87)
VBUS_D: length 44.3
  TOP w0.33: D1.1 v1(1.34,28.6)
  TOP w0.635: v1(15.88,11.05) 11.36,11.05 v1(10.22,9.91)
  TOP w0.762: v1(14.73,22.73) 14.73,15.48 v1(16.88,13.34)
  POWER w0.33: v1(9.27,22.48) 7.48,24.27 7.48,27.51 5.94,29.06 2.82,29.06 2.36,28.6 v1(1.34,28.6)
  BOTTOM w0.381: v1(14.73,22.73) 13.57,23.89 10.68,23.89 v1(9.27,22.48)
  BOTTOM w0.508: D8.1 17.78,23.19 18.43,22.54 R9.2 C10.1 ; v1(10.22,9.91) C3.2
  BOTTOM w0.635: C3.2 10.16,9.33 U2.4
  BOTTOM w0.762: D8.1 17.19,22.99 16.08,22.99 Q3.1 v1(14.73,22.73)
VCC: length 1.2
  BOTTOM w0.254: R8.1 11.42,21.01 U3.6
VCC_IN: length 39
  TOP w0.254: J7.9 48.3,24.86 48.27,24.89 48.27,24.91 48.19,24.98 48.19,25.1 47.69,25.61 46.29,25.61 45.09,25.61 41.66,22.17 v1(41.66,20.95)
  BOTTOM w0.381: v1(41.66,20.95) 40.34,19.63 36.17,19.63 33.78,17.25 33.78,12.06 31.95,10.24 22.76,10.24 20.93,12.06 D7.1
VDD: length 92.2
  TOP w0.203: v1(21.79,28.63) 21.79,28.63 21.4,29.02 J5.17 ; v1(21.21,25.91) 21.4,26.1 J5.18 ; v1(39.69,1.5) 39.69,1.21 39.85,1.05 J4.9 ; v1(39.24,5.08) 39.02,4.85 39.02,4.81 38.74,4.53 38.74,3.71 38.65,3.62 J4.16 38.65,1.97 38.5,1.82 v1(38.5,1.27) ; v1(38.5,14.27) 38.5,14.82 38.65,14.97 J6.16 38.65,16.95 38.79,17.09 38.79,17.83 v1(39.12,18.16)
  TOP w0.254: v1(49.78,25.27) 49.9,25.16 J7.17 ; J6.9 39.85,14.01 39.79,14.07 39.79,14.36 39.74,14.41 39.74,14.43 v1(39.68,14.49) ; v1(49.78,21.08) 49.9,21.2 J7.18
  TOP w0.33: v1(34.67,17.4) 34.23,16.95 30.8,16.95 29.84,16 v1(23.75,16) v1(23.75,17.02)
  TOP w0.889: v1(35.45,21.19) v1(35.05,21.59) 33.54,23.1 33.03,23.1 v1(33.02,23.11) v1(32.26,23.11)
  POWER w0.508: v1(49.78,21.08) 49.4,21.47 49.4,23.91 49.78,24.29 v1(49.78,25.27) 48.9,24.38 46.99,24.38 46.63,24.03 40.67,24.03 39.95,24.74 36.72,24.74 J12.1
  POWER w0.635: v1(39.24,5.08) 39,5.32 39,5.35 38.62,5.73 37.45,5.73 35.05,8.13 35.05,10.41 36.32,11.68 v1(38.49,11.68)
  POWER w0.762: J12.1 34.09,25.96 33.02,24.89
  BOTTOM w0.203: v1(39.24,5.08) 39.81,4.51 39.81,3.66 39.85,3.63 J8.16 ; J9.16 24.26,15.95 24.21,16 v1(23.75,16) ; J8.9 38.65,1.12 v1(38.5,1.27) 38.94,1.7 39.51,1.7 39.69,1.52 v1(39.69,1.5) ; 38.65,12.94 38.65,14.12 v1(38.5,14.27) 38.9,14.67 39.51,14.67 v1(39.68,14.49) ; v1(23.75,17.02) 23.62,17.14 23.25,17.14 23.25,17.15 J9.9
  BOTTOM w0.279: v1(21.21,25.91) 21.21,26.05 21.99,26.83 21.99,27.89 21.8,28.08 21.8,28.62 v1(21.79,28.63)
  BOTTOM w0.33: v1(21.97,23.71) 21.97,23.75 22.1,23.88 R12.2 ; C23.2 49.72,25.21 v1(49.78,25.27) ; R11.2 v1(27.18,23.75) ; v1(21.21,25.91) 21.08,25.78 C24.2 ; R13.2 23.24,23.73 v1(23.22,23.71) ; C25.2 45.87,11.3 45.67,11.51 40.4,11.51 40.08,11.19 38.99,11.19 v1(38.49,11.68) 38.49,12.78 38.65,12.94 ; R10.2 v1(25.02,23.71)
ADC_VBAT: length 32.2
  TOP w0.381: v1(10.65,12.94) 11.04,13.33 11.94,13.33 12.72,12.56 17.38,12.56 17.78,12.95 17.78,15.37 17.65,15.49 17.65,18.93 17.31,19.28 v1(16.76,19.28) ; v1(9.02,11.43) 8.13,10.54 v1(6.22,10.54) ; v1(20.45,22.62) v1(20.45,21.46)
  BOTTOM w0.305: v1(20.45,22.62) 22.83,22.62 24.13,23.93 R7.1
  BOTTOM w0.381: v1(20.45,21.46) 20.45,20.92 18.81,19.28 v1(16.76,19.28) ; R3.2 v1(6.22,10.54) R4.1 ; v1(10.65,12.94) 10.65,12.4 10.07,11.82 9.4,11.82 v1(9.02,11.43)
AIN0: length 38.3
  TOP w0.127: J5.21 22.2,29.11 22.47,28.84 22.47,28.66 22.58,28.54 22.95,28.18 23,28.18 v1(23.37,27.81) 23.72,27.46 25.87,27.46 26.27,27.86 27.48,27.86 28,27.34 28,26.22 27.82,26.04 27.82,25.4 28.19,25.03 30.82,25.03 33.22,27.43 43.65,27.43 43.83,27.61 v1(44.27,27.61) ; J7.21 50.7,25.09 50.68,25.11 50.68,25.52 v1(49.91,26.29)
  BOTTOM w0.127: R7.2 24.13,26.8 23.37,27.56 v1(23.37,27.81) ; v1(49.91,26.29) 49.5,26.7 48.8,26.7 48.57,26.92 44.96,26.92 v1(44.27,27.61)
AIN1: length 65.8
  TOP w0.127: v1(22.37,21.47) 22.37,22.22 22.6,22.44 22.6,25.78 22.2,26.17 J5.22 ; v1(50.26,22.86) 50.7,22.42 J7.22 50.7,21.12 49.41,19.83 49.41,16.31 48.75,15.65 48.75,14.93 48.78,14.9 48.78,14.23 46.93,12.38 46.93,11.3 46.8,11.17 42.77,7.14 36.35,7.14 32.93,10.57 31.46,10.57 27.06,14.98 23.89,14.98 22.71,16.16 22.71,17.35 20.76,19.3 v1(20.2,19.3)
  POWER w0.127: v1(50.52,26.46) 50.52,24.11 50.1,23.69 50.1,23.02 v1(50.26,22.86)
  BOTTOM w0.127: v1(22.37,21.47) 21.86,20.96 v1(20.2,19.3) ; v1(50.52,26.46) 50.06,26.92 48.9,26.92 48.62,27.2 46.96,27.2 J11.1
BOOT0: length 18.1
  TOP w0.127: J5.23 22.6,29.15 22.7,29.06 22.7,28.75 22.81,28.64 23.04,28.41 23.33,28.41 23.76,27.98 23.76,27.94 24.01,27.69 25.77,27.69 26.18,28.09 27.58,28.09 28.23,27.44 28.23,26.12 28.05,25.94 28.05,25.49 28.28,25.26 30.73,25.26 33.97,28.5 J10.1
EN: length 2.7
  BOTTOM w0.254: U3.5 10.92,21.02 R8.2 9.33,21.21 C12.2
GREEN_POWER: length 7.7
  TOP w1.27: v1(13.08,8.94) v1(13.08,8.26) 13.08,7.68 P2.1
I2C1_SCL: length 91.8
  TOP w0.127: v1(31.11,24.13) 30.73,23.75 30.66,23.75 30.64,23.73 29.3,23.73 29.29,23.75 28.07,23.75 26.15,21.83 25.45,21.83 25.43,21.85 25.08,21.85 25.06,21.83 24.59,21.83 24.02,21.26 v1(23.6,21.26) 23.3,20.96 22.33,20.96 21.98,21.31 21.98,22.36 22.37,22.75 22.37,25.45 v1(22,25.81) 21.94,25.81 21.8,25.95 J5.20 ; J4.7 v1(40.25,1.26) ; v1(48.39,14.73) 48.39,15.61 49.19,16.41 49.19,19.92 50.3,21.04 J7.20 50.3,22.26 50.09,22.47 49.86,22.7 49.86,22.85 49.22,23.49 v1(48.8,23.49) ; J6.7 v1(40.25,14.26)
  POWER w0.127: v1(40.25,1.26) 40.25,1.68 40,1.93 37.74,1.93 37.48,1.66 36.84,1.66 36.42,1.24 35.85,1.24 35.43,1.65 v1(34.8,1.65)
  BOTTOM w0.127: R12.1 22,25.31 v1(22,25.81) ; v1(48.39,14.73) 47.66,14.73 45.37,12.45 45,12.45 42.06,12.45 v1(40.25,14.26) 40.25,14.56 39.87,14.94 38.61,14.94 38.11,14.43 38.11,12.91 36.02,10.82 34.8,9.6 v1(34.8,1.65) ; J9.7 23.15,17.55 23.29,17.41 24.3,17.41 24.65,17.77 24.65,18.27 23.88,19.05 23.88,20.52 23.6,20.8 v1(23.6,21.26) ; J8.7 38.25,0.96 38.11,1.11 38.11,1.43 38.64,1.97 39.96,1.97 40.25,1.68 v1(40.25,1.26) ; v1(48.8,23.49) 48.51,23.79 48.29,24 42.54,24 J12.3 39.44,24.82 31.8,24.82 v1(31.11,24.13)
I2C1_SDA: length 100.9
  TOP w0.127: J5.19 21.8,29.17 22.01,28.96 22.02,28.96 22.19,28.79 22.19,28.49 22.3,28.38 v1(22.3,28.27) ; v1(21.84,23.11) 21.84,22.69 21.75,22.59 21.75,21.21 22.23,20.73 24.04,20.73 24.76,21.45 v1(25.18,21.45) 26.14,21.45 28.13,23.44 31.08,23.44 32.37,24.74 41.9,24.74 J12.4 43.79,26.63 48.95,26.63 v1(49.3,26.29) 49.78,25.81 49.94,25.81 50.31,25.44 50.31,25.11 50.3,25.1 J7.19 ; J6.8 v1(40.25,17.02) ; J4.8 v1(40.25,4.32)
  POWER w0.127: v1(49.3,26.29) 49.69,25.89 49.76,25.89 50.29,25.36 50.29,24.2 49.86,23.78 49.86,21.77 50.42,21.21 50.42,20.19 47.57,17.35 42.62,17.35 41.67,16.4 40.87,16.4 v1(40.25,17.02) ; v1(33.62,5.37) 34.85,4.14 35.05,4.14 35.92,3.27 39.2,3.27 v1(40.25,4.32)
  BOTTOM w0.127: J8.8 38.25,3.4 37.92,3.73 37.92,5.2 38.19,5.48 39.41,5.48 40.25,4.63 v1(40.25,4.32) ; v1(33.62,5.37) 34.04,5.79 34.04,9.81 36.65,12.42 36.65,14.81 37.21,15.37 37.21,17.3 37.59,17.68 38.52,17.68 38.55,17.71 39.55,17.71 v1(40.25,17.02) ; 23.22,25.21 23.18,25.21 22.73,24.77 22.73,23.91 22.13,23.31 22.05,23.31 v1(21.84,23.11) ; 23.22,25.21 R13.1 ; 23.22,25.21 23.22,27.28 22.97,27.52 22.97,28.01 22.72,28.27 v1(22.3,28.27) ; v1(25.18,21.45) 27.55,19.09 27.55,17.78 27.16,17.38 26,17.38 25.83,17.55 J9.8
I2C2_SCL: length 42.2
  TOP w0.127: v1(29.46,18.82) v1(29.46,19.94) ; J5.36 v1(25,25.91) ; J7.36 53.5,22.65 53.5,22.65 53.5,23.21 v1(53.09,23.62)
  BOTTOM w0.127: v1(25,25.91) 25.02,25.89 R10.1 25.49,25.21 25.64,25.06 25.64,23.76 28.94,20.46 28.95,20.46 v1(29.46,19.94) ; v1(29.46,18.82) 33.48,18.82 34.88,20.22 39.59,20.22 40.95,21.58 42.11,21.58 43.34,20.35 44.57,20.35 44.7,20.48 46.01,21.79 46.14,21.92 48.42,21.92 49.2,22.7 49.2,23.19 50.3,24.29 50.3,25.38 50.82,25.9 50.91,25.9 51.95,25.9 52.31,25.53 52.31,24.39 v1(53.09,23.62)
I2C2_SDA: length 35.1
  TOP w0.127: J5.35 25,28.96 25.26,28.7 v1(25.27,28.7) ; J7.35 53.5,26.26 52.55,27.2 34.11,27.2 31.71,24.8 28.09,24.8 27.6,25.3 27.6,25.4 v1(27.18,25.82)
  BOTTOM w0.127: v1(25.27,28.7) 25.27,28.23 27.18,26.33 v1(27.18,25.82) R11.1
IO1: length 90.2
  TOP w0.127: v1(50.5,23.53) 50.93,23.96 52.17,23.96 52.3,24.09 J7.29 52.3,25.88 v1(52.58,26.16) ; J4.12 39.45,3.95 39.63,4.12 39.63,4.9 40.03,5.3 40.03,5.52 40.47,5.97 v1(40.89,5.97) ; v1(41.27,18.54) 40.88,18.15 40.19,18.15 39.85,17.81 39.85,16.8 39.85,16.79 J6.10 ; v1(24,28.73) 23.98,28.73 23.87,28.84 23.87,29.09 23.8,29.15 J5.29
  POWER w0.127: v1(33.61,3.23) 34.03,3.23 34.84,2.41 35.94,2.41 36.34,2.81 40.11,2.81 41.45,4.15 41.45,4.91 40.89,5.46 v1(40.89,5.97)
  BOTTOM w0.127: v1(24,28.73) 24.42,28.73 24.79,29.1 25.85,29.1 25.85,29.11 26.18,29.11 26.19,29.1 26.4,29.1 29.46,26.04 30.99,26.04 34.54,29.58 47.12,29.58 J11.2 49.52,27.18 51.56,27.18 v1(52.58,26.16) ; v1(50.5,23.53) 50.23,23.26 50.09,23.26 49.78,22.95 49.78,22.63 48.61,21.46 46.33,21.46 43.41,18.54 v1(41.27,18.54) 40.57,19.24 37.62,19.24 34.42,16.04 34.42,12.09 32.37,10.04 32.37,4.46 v1(33.61,3.23)
IO2: length 93.8
  TOP w0.127: J4.10 39.85,4.02 39.85,4.03 39.85,4.81 40.25,5.21 40.25,5.33 40.5,5.57 41.51,5.57 v1(41.92,5.98) ; v1(40.51,18.54) 40.26,18.54 39.63,17.9 39.63,16.89 39.45,16.72 J6.12 ; v1(21.84,15.69) 22.28,15.69 23.51,14.45 26.44,14.45 v1(26.54,14.35) 31.14,9.75 v1(32.77,9.75) ; J7.30 52.3,22.45 52.15,22.6 51.91,22.83 51.91,22.83 51.48,23.27 51.47,23.27 v1(51.17,23.56) ; v1(37.97,6.48) 35.43,3.94 v1(33.66,3.94) ; v1(24.89,22.23) 24.51,22.61 24.51,24.26 23.8,24.97 J5.30
  POWER w0.127: v1(53.34,27.05) 53.34,26.2 51.17,24.03 v1(51.17,23.56)
  BOTTOM w0.127: J11.3 52.19,27.05 v1(53.34,27.05) ; R23.1 19.91,15.49 19.98,15.43 R24.1 21.17,15.43 21.42,15.69 v1(21.84,15.69) ; v1(26.54,14.35) 29.1,16.91 29.1,18.1 25.27,21.93 25.19,21.93 v1(24.89,22.23) ; v1(33.66,3.94) 32.77,4.83 v1(32.77,9.75) 34.65,11.63 34.65,15.95 37.71,19.01 40.04,19.01 v1(40.51,18.54) 41.35,17.71 47.64,17.71 50.18,20.25 50.18,22.19 50.65,22.66 50.65,23.13 51.09,23.56 v1(51.17,23.56) ; v1(41.92,5.98) 41.41,6.48 v1(37.97,6.48)
IO3: length 64.9
  TOP w0.127: v1(52.44,23.59) 52.7,23.85 J7.31 52.7,25.1 52.69,25.11 52.69,25.72 52.97,26 52.97,26.33 52.32,26.97 34.21,26.97 31.81,24.57 31.62,24.57 27.75,24.57 v1(26.54,25.78) ; v1(50.16,14.99) 49.24,14.06 49.24,14.04 47.42,12.22 47.42,11.03 47.29,10.89 43,6.6 39.38,6.6 38.35,5.58 v1(38.35,5.08) ; J5.31 24.2,29.08 24.39,28.89 24.39,28.7 24.4,28.69 24.4,28.43 v1(24.74,28.08)
  POWER w0.127: v1(50.16,14.99) 51.56,16.38 51.56,21.65 52.7,22.79 52.7,23.33 v1(52.44,23.59)
  BOTTOM w0.127: v1(24.74,28.08) 25.04,27.79 25.17,27.79 26.54,26.42 v1(26.54,25.78) ; v1(38.35,5.08) 38.84,4.6 38.84,3.81 39.05,3.59 J8.12
IO4: length 70.2
  TOP w0.127: v1(52.31,22.99) 52.7,22.6 J7.32 ; v1(50.67,16.13) 50.67,14.93 48.51,12.78 48.51,11.8 47.65,10.93 43.09,6.38 43.08,6.38 43.07,6.37 41.75,6.37 41.75,6.36 39.46,6.36 38.75,5.65 38.75,4.92 38.31,4.48 v1(38.31,3.89) ; J5.32 24.2,25.13 25.61,23.71 v1(25.61,22.23)
  POWER w0.127: v1(52.31,22.99) 51.31,21.99 51.31,16.76 v1(50.67,16.13)
  BOTTOM w0.127: v1(25.61,22.23) 29.07,18.77 29.07,18.66 29.3,18.43 31.96,18.43 31.97,18.43 33.42,18.43 34.98,19.99 39.69,19.99 41.05,21.35 42.01,21.35 43.24,20.12 44.66,20.12 44.93,20.38 46.24,21.69 48.52,21.69 49.43,22.6 49.43,23.09 50.53,24.2 50.53,25.29 50.68,25.44 50.91,25.67 51,25.67 51.85,25.67 52.08,25.44 52.08,25.11 52.05,25.07 52.05,23.26 v1(52.31,22.99) ; J8.10 38.65,3.56 v1(38.31,3.89)
IO5: length 61.4
  TOP w0.127: v1(28.07,17.16) 28.07,17.62 28.03,17.66 28.03,17.98 28.39,18.35 29.55,18.35 29.86,18.66 29.86,20.05 30.15,20.33 30.33,20.33 30.35,20.35 v1(30.77,20.35) 30.98,20.56 33.23,20.56 35.71,18.08 v1(38.35,18.08) ; v1(26.02,28.71) 26.01,28.7 25.83,28.7 25.4,29.13 J5.37 ; J7.37 v1(53.9,25.35)
  POWER w0.127: v1(38.35,18.08) 38.75,17.68 38.75,17.24 39.82,16.17 42.68,16.17 43.63,17.12 47.7,17.12 49.54,15.28 49.54,13.64 49.28,13.37 v1(49.28,12.95)
  BOTTOM w0.127: v1(53.9,25.35) 54.88,24.37 54.88,22.95 54.03,22.1 52.1,22.1 51.58,21.57 51.58,18 49.66,16.08 49.66,13.34 v1(49.28,12.95) ; v1(26.02,28.71) 26.02,27.83 27.67,26.18 27.67,24.18 30.24,21.62 30.24,20.88 v1(30.77,20.35) ; v1(28.07,17.16) 27.66,16.75 J9.12
IO6: length 49.8
  TOP w0.127: v1(28.43,17.82) 29.35,17.82 30.31,18.79 v1(30.31,19.94) 30.96,19.94 31.1,20.08 31.1,20.1 31.33,20.33 33.13,20.33 35.64,17.83 37.8,17.83 v1(38.35,17.27) ; v1(53.89,22.86) 53.89,22.82 53.9,22.81 J7.38 ; J5.38 25.4,25.4 v1(26.04,24.77)
  POWER w0.127: v1(38.35,17.27) 38.35,16.85 39.28,15.93 42.76,15.93 43.73,16.89 47.37,16.89 v1(49.15,15.11)
  BOTTOM w0.127: v1(53.89,22.86) 53.35,22.33 52.01,22.33 51.35,21.67 51.35,18.1 49.15,15.89 v1(49.15,15.11) ; v1(26.04,24.77) 26.04,23.69 29.03,20.69 29.57,20.69 v1(30.31,19.94) ; v1(28.43,17.82) 27.92,17.82 27.25,17.15 J9.10
IO7: length 55.5
  TOP w0.127: v1(20.7,18.8) 21.45,18.05 21.63,18.05 21.86,17.82 22.48,17.2 22.48,16.07 23.8,14.75 26.71,14.75 31.17,10.29 32.88,10.29 36.3,6.87 42.94,6.87 47.19,11.12 47.19,12.31 49.01,14.13 49.01,14.16 49.64,14.79 49.64,17.12 49.64,19.73 51.1,21.19 J7.24 ; v1(22.98,21.41) 22.98,21.83 22.83,21.99 22.83,26.07 22.6,26.3 J5.24
  BOTTOM w0.127: v1(22.98,21.41) 21,19.43 21,19.09 v1(20.7,18.8)
IO8: length 56.2
  TOP w0.127: J5.16 21,26.33 19.85,25.18 18.07,25.18 17.77,24.88 17.77,24.73 17.55,24.51 17.55,22.83 22.94,17.44 22.94,16.26 23.99,15.2 27.42,15.2 31.83,10.79 33.02,10.79 36.45,7.37 42.67,7.37 46.7,11.4 46.7,12.47 47.98,13.75 47.98,15.53 48.16,15.7 48.96,16.5 48.96,20.81 49.5,21.36 J7.16
LED1: length 53.3
  TOP w0.127: J5.14 20.6,26.29 19.72,25.41 17.98,25.41 17.54,24.97 17.54,24.83 17.32,24.61 17.32,21.74 18.39,20.67 18.39,16.16 22.87,11.68 v1(24.13,11.68) ; J7.14 49.1,22.53 48.81,22.82 v1(48.81,22.86) ; v1(32.13,18.03) v1(33.4,19.3)
  BOTTOM w0.127: Q1.1 24.14,11.68 v1(24.13,11.68) 24.89,12.45 26.54,12.45 v1(32.13,18.03) ; v1(48.81,22.86) 48.09,22.15 46.05,22.15 45.91,22.01 45.78,21.88 45.78,21.88 44.47,20.57 43.43,20.57 42.2,21.81 40.86,21.81 39.5,20.45 34.54,20.45 v1(33.4,19.3)
LED2: length 58.3
  TOP w0.127: J5.15 21,29.03 21.33,28.7 21.33,28.48 22.13,27.68 v1(22.58,27.68) ; v1(21.23,23.15) 21.23,21.89 21.24,21.88 v1(21.24,21.46) 21.24,21.04 21.78,20.5 24.44,20.5 24.91,20.97 25.98,20.97 28.23,23.22 31.17,23.22 32.47,24.51 43.26,24.51 44.88,26.13 45.03,26.13 48.56,26.13 49.39,25.3 49.39,25.11 49.5,25 J7.15 ; v1(19.43,18.8) 19.01,18.8 18.78,18.57 18.78,16.09 22.05,12.83 24.9,12.83 v1(26.04,11.68)
  BOTTOM w0.127: Q2.1 v1(26.04,11.68) ; v1(21.24,21.46) 21.24,21.04 19.43,19.24 v1(19.43,18.8) ; v1(21.23,23.15) 21.58,23.5 21.58,23.91 21.6,23.94 21.6,25.98 22.58,26.95 v1(22.58,27.68)
RESET: length 74.8
  TOP w0.127: J5.13 20.6,29.11 21.1,28.61 21.1,28.08 v1(21.49,27.69) ; v1(20.45,23.24) 20.84,22.85 20.84,21.11 21.78,20.18 25.51,20.18 28.32,22.99 31.27,22.99 32.56,24.28 43.35,24.28 44.97,25.9 45,25.9 46.17,25.9 48.47,25.9 49.1,25.27 J7.13 ; v1(3.94,21.59) 4.45,22.1 4.45,22.26 6.56,24.38 8.89,24.38 v1(10.67,26.16) ; v1(3.61,12.78) 3.52,12.69 J3.1
  BOTTOM w0.127: v1(3.94,21.59) 3.3,20.95 3.3,15.37 4.04,14.63 4.04,13.21 v1(3.61,12.78) 3.94,12.45 C14.2 ; v1(10.67,26.16) 14.73,26.16 17.91,29.34 19.84,29.34 v1(21.49,27.69) 21.49,26.8 20.45,25.75 v1(20.45,23.24)
RXD0: length 40.2
  TOP w0.155: J7.12 48.7,22.35 48.2,22.85 v1(48.19,22.85) ; v1(19.95,27.58) 19.95,27.55 20.2,27.3 J5.12
  BOTTOM w0.155: v1(19.95,27.58) 20.16,27.37 20.16,26.91 19.75,26.51 19.75,22.34 20.16,21.93 23.2,21.93 23.9,22.63 25.79,22.63 29.18,19.25 31.89,19.25 36.75,24.1 38.99,24.1 39.83,23.26 47.78,23.26 v1(48.19,22.85)
RXD1: length 81.9
  TOP w0.127: v1(31.5,19.94) 31.5,19.39 29.38,17.27 v1(28.7,17.27) ; J7.34 v1(53.1,22.86) ; J4.24 v1(37.05,3.74) ; J5.34 24.6,25.44 25.89,24.14 27.34,24.14 27.36,24.13 v1(29.46,24.13)
  BOTTOM w0.127: v1(28.7,17.27) 28.7,17.18 25.88,14.35 J9.24 ; v1(37.05,3.74) 37.05,6.11 38.24,7.3 43.75,7.3 46.74,10.29 47.09,10.29 48.78,11.98 48.78,14.9 48.75,14.93 48.75,15.82 51.12,18.19 51.12,21.76 51.91,22.56 52.8,22.56 v1(53.1,22.86) 53.48,23.24 53.48,23.86 52.69,24.65 52.69,25.48 52.54,25.63 52.04,26.13 50.72,26.13 50.49,25.89 48.9,25.89 48.32,26.47 44.86,26.47 43.81,27.51 43.81,27.81 J10.4 42.08,27.46 33.21,27.46 29.88,24.13 v1(29.46,24.13) 31.5,22.1 v1(31.5,19.94)
SPI_CLK: length 82.5
  TOP w0.127: J5.26 23,26.22 23.09,26.13 23.09,24.92 23.77,24.23 v1(23.77,21.84) ; v1(26.92,18.03) 27.94,19.05 27.94,19.3 29.21,20.56 29.73,20.56 30.19,21.02 33.42,21.02 35.21,19.23 41.47,19.23 41.9,18.8 41.9,18.16 41.66,17.91 v1(41.66,17.02) 41.05,16.41 J6.4 ; J7.26 51.5,21.02 50.04,19.56 v1(50.04,19.05) ; J4.4 v1(41.05,4.32)
  POWER w0.127: v1(41.05,4.32) 39.78,3.04 35.69,3.04 35.05,3.68 34.54,3.68 v1(33.62,4.61)
  BOTTOM w0.127: v1(50.04,19.05) 48.47,17.48 42.12,17.48 v1(41.66,17.02) 41.36,17.32 41.18,17.32 39.71,18.79 38.05,18.79 36.75,17.49 36.75,15.56 36.19,15 36.19,12.61 33.22,9.64 33.22,5.01 v1(33.62,4.61) ; J8.4 37.45,5.38 38,5.93 40.36,5.93 41.05,5.24 v1(41.05,4.32) ; v1(26.92,18.03) 26.63,18.33 26.46,18.33 26.44,18.35 J9.4 24.9,18.35 24.21,19.04 24.21,21.41 v1(23.77,21.84)
SPI_CS: length 103.5
  TOP w0.127: v1(29.21,21.34) 26.39,18.52 24.1,18.52 v1(23.62,18.04) ; v1(51.08,25.27) 51.5,24.85 J7.25 ; J5.25 23,29.01 23.04,28.97 23.04,28.97 v1(23.21,28.8) ; v1(19.18,18.16) 21.08,16.26 21.08,15.37 21.44,15.01 21.97,15.01 23.03,13.95 26.06,13.95 26.28,13.73 26.33,13.73 32.37,7.69 32.37,2.76 32.98,2.14 33.54,2.14 v1(34.04,1.65) ; v1(41.15,14.99) 41.15,14.57 41.05,14.47 J6.3 ; J4.3 v1(41.05,1.26)
  POWER w0.127: v1(34.04,1.65) 34.43,1.26 35.24,1.26 35.64,0.86 40.65,0.86 v1(41.05,1.26)
  BOTTOM w0.127: v1(51.08,25.27) 51.08,24.49 51.56,24 51.56,22.92 50.66,22.02 50.66,18.38 45.19,12.9 42.81,12.9 41.15,14.57 v1(41.15,14.99) 40.74,15.4 38.28,15.4 37.45,14.57 37.45,12.9 35.56,11.01 34.3,9.75 34.3,3.37 33.87,2.94 33.64,2.7 33.64,2.05 v1(34.04,1.65) ; v1(23.62,18.04) 23.32,18.34 23.32,18.34 23.31,18.35 J9.3 20.89,18.35 20.7,18.16 v1(19.18,18.16) ; v1(23.21,28.8) 23.73,28.27 23.73,28.01 23.76,27.98 23.76,27.7 25.41,26.06 25.41,26.03 26.48,24.96 26.48,23.56 28.71,21.34 v1(29.21,21.34) ; v1(41.05,1.26) 41.05,1.94 40.56,2.43 38.31,2.43 37.45,1.57 J8.3
SPI_MISO: length 97.2
  TOP w0.127: v1(34.1,2.48) 33.8,2.77 33.5,2.77 33.16,3.11 33.16,3.56 32.76,3.95 32.76,7.62 26.42,13.96 26.38,13.96 26.11,14.22 23.11,14.22 22.05,15.29 21.68,15.29 21.45,15.52 21.45,17.22 21.46,17.23 v1(21.46,17.65) ; v1(51.69,25.27) 51.69,25.27 51.9,25.06 J7.27 ; v1(24.13,28.13) 23.93,28.33 23.83,28.33 23.6,28.56 23.6,28.85 23.6,28.85 23.6,28.96 23.49,29.07 23.4,29.17 J5.27 ; J4.5 v1(40.65,1.78) ; v1(24.26,17.93) 24.62,18.29 26.61,18.29 29.11,20.79 29.3,20.79 v1(29.84,21.34) ; v1(40.39,14.99) 40.65,14.72 J6.5
  POWER w0.127: v1(40.65,1.78) 40.14,2.29 37.72,2.29 37.32,1.89 36.89,1.89 36.73,2.05 34.53,2.05 v1(34.1,2.48)
  BOTTOM w0.127: v1(40.65,1.78) 40.23,2.2 38.4,2.2 37.85,1.65 J8.5 ; v1(24.13,28.13) 25.64,26.62 25.64,26.13 26.71,25.06 26.71,23.66 28.64,21.73 29.45,21.73 v1(29.84,21.34) ; v1(24.26,17.93) 24.26,17.77 24.13,17.64 23.45,17.64 23.43,17.66 23.37,17.66 23.18,17.86 23.17,17.86 23.08,17.95 J9.5 22.18,17.95 21.88,17.65 v1(21.46,17.65) ; v1(51.69,25.27) 51.69,24.38 51.79,24.28 51.79,22.82 50.89,21.92 50.89,18.28 45.28,12.67 45.09,12.67 42.7,12.67 v1(40.39,14.99) 40.39,15.04 40.26,15.17 38.37,15.17 37.85,14.65 37.85,12.97 35.79,10.91 34.54,9.67 34.54,2.92 v1(34.1,2.48)
SPI_MOSI: length 84.9
  TOP w0.127: J4.6 v1(40.65,5.08) ; v1(26.16,17.78) 26.58,17.78 26.72,17.64 27.09,17.64 28.7,19.25 28.7,19.74 29.3,20.33 29.83,20.33 30.28,20.79 33.32,20.79 35.18,18.94 41.44,18.94 41.67,18.71 41.67,18.38 40.89,17.6 v1(40.89,17.02) 40.65,16.77 J6.6 ; v1(51.05,22.96) 51.35,22.66 51.68,22.66 51.9,22.44 J7.28 ; v1(24.26,22.23) 24.26,24.13 23.4,24.99 J5.28
  POWER w0.127: v1(33.64,6.13) 35.46,4.32 37.13,4.32 37.95,3.5 39,3.5 39.85,4.35 39.85,4.48 40.16,4.78 40.35,4.78 v1(40.65,5.08)
  BOTTOM w0.127: J9.6 25.99,17.95 v1(26.16,17.78) 26.62,17.78 26.76,17.64 27.09,17.64 27.32,17.87 27.32,18.92 25.27,20.97 25.09,20.97 24.26,21.8 v1(24.26,22.23) ; J8.6 37.85,3.47 37.69,3.64 37.69,5.3 38.1,5.7 40.03,5.7 v1(40.65,5.08) ; v1(33.64,6.13) 33.64,9.74 36.42,12.52 36.42,14.9 36.98,15.46 36.98,17.4 38.14,18.56 39.36,18.56 v1(40.89,17.02) 41.42,16.5 43.17,16.5 43.81,17.14 48.69,17.14 50.43,18.89 50.43,22.12 50.92,22.6 50.92,22.83 v1(51.05,22.96)
SW1: length 55.4
  TOP w0.127: J5.10 19.8,26.4 19.15,25.76 18,25.76 17.31,25.06 17.31,24.92 17.09,24.7 17.09,21.64 18.16,20.57 18.16,16.07 23.05,11.18 v1(28.32,11.18) ; J7.10 48.3,20.79 48.69,20.4 48.69,16.56 47.75,15.62 47.75,13.84 45.08,11.18 32,11.18 v1(30.86,12.32)
  BOTTOM w0.127: v1(28.32,11.18) 29.72,11.18 v1(30.86,12.32)
TXD0: length 41.1
  TOP w0.155: J5.11 20.2,29.08 20.53,28.75 20.62,28.75 20.86,28.51 20.86,27.97 v1(20.57,27.69) ; J7.11 48.7,24.05 v1(48.19,23.54)
  BOTTOM w0.155: v1(20.57,27.69) 20.45,27.56 20.45,26.8 20.04,26.39 20.04,22.46 20.28,22.22 23.08,22.22 23.79,22.92 25.9,22.92 29.29,19.53 31.77,19.53 36.63,24.39 39.11,24.39 39.95,23.54 v1(48.19,23.54)
TXD1: length 86.4
  TOP w0.127: J7.33 53.1,25.26 v1(53.09,25.27) ; v1(30.64,21.46) 30.61,21.46 30.33,21.74 29.05,21.74 26.06,18.75 v1(23.45,18.75) ; J4.1 v1(41.45,1.78) ; v1(54.48,29.08) 53.98,29.59 41.67,29.59 J10.3 39.49,29.59 34.54,29.59 30.61,25.65 v1(28.45,25.65) 28.45,25.78 28.46,25.79 28.46,27.53 27.94,28.05 27.67,28.32 26.21,28.32 26.21,28.32 26.08,28.32 26.07,28.31 25.11,28.31 24.62,28.79 24.62,28.99 24.6,29.01 J5.33
  POWER w0.127: v1(53.09,25.27) 51.69,23.88 51.69,22.86 51.05,22.23 51.05,17.14 49.77,15.86 49.77,14.82 49.77,14.82 49.77,14.49 v1(50.29,13.97)
  BOTTOM w0.127: v1(41.45,1.78) 42.93,1.78 43.81,2.67 43.81,7.04 46.83,10.06 47.27,10.06 50.29,13.08 v1(50.29,13.97) ; v1(30.64,21.46) 30.64,22.07 28.45,24.26 v1(28.45,25.65) ; J9.1 v1(23.45,18.75) ; v1(53.09,25.27) 53.74,25.92 53.74,26.99 54.48,27.74 v1(54.48,29.08)
USB+: length 67.7
  TOP w0.203: U4.1 8.61,18.49 U5.1 8.46,18.45 8.36,18.35 7.94,18.35 7.85,18.44 ; v1(18.25,24.13) 18.14,24.01 18.14,23.1 21.92,19.32 22.95,19.32 23.26,19.62 25.52,19.62 28.32,22.42 32.85,22.42 34.79,20.47 42.19,20.47 44.94,23.22 46.66,23.22 46.93,23.48 47.46,23.48 47.9,23.92 J7.7 ; v1(19.05,28.46) 19.12,28.46 19.4,28.74 J5.7 ; 7.85,18.44 v1(7.85,18.54) ; 7.85,18.44 J1.A6 ; v1(4.95,18.16) 4.99,18.19 J1.B6
  BOTTOM w0.203: v1(4.95,18.16) 5.08,18.29 5.39,18.29 6.64,17.04 7.76,17.04 8.26,17.54 8.26,18.13 v1(7.85,18.54) 7.68,18.38 7.45,18.39 6.87,18.99 6.87,20.81 8.19,22.14 8.19,22.67 10.41,24.89 15.62,24.89 16.26,24.26 18.13,24.26 v1(18.25,24.13) 19.05,24.93 19.05,27.23 19.48,27.66 19.48,27.92 19.48,27.93 19.48,28.03 19.05,28.45 v1(19.05,28.46)
USB-: length 67.2
  TOP w0.203: J5.8 19.4,27.56 19.19,27.77 19.12,27.77 v1(19.05,27.84) ; J7.8 47.9,22.53 47.76,22.67 47.76,22.75 47.75,22.75 47.75,22.84 47.42,23.17 47.06,23.17 46.8,22.9 45.07,22.9 42.32,20.15 34.66,20.15 32.72,22.1 28.45,22.1 25.65,19.3 23.39,19.3 23.08,19 21.79,19 17.82,22.97 17.82,24.31 18.24,24.72 v1(18.24,24.78) ; U4.2 8.6,17.79 U5.2 8.46,17.81 8.23,18.04 7.97,18.04 v1(7.83,17.89) 7.77,17.94 J1.A7 ; v1(4.95,18.77) 5.03,18.69 J1.B7
  BOTTOM w0.203: v1(4.95,18.77) 5.06,18.67 5.46,18.67 6.77,17.36 7.63,17.36 7.84,17.56 7.84,17.88 v1(7.83,17.89) 7.67,18.07 7.31,18.08 6.55,18.87 6.55,20.94 7.87,22.27 7.87,22.8 10.28,25.21 15.75,25.21 16.39,24.57 18.03,24.57 v1(18.24,24.78) 18.73,25.27 18.73,27.51 v1(19.05,27.84)
N577502: length 28.9
  TOP w0.127: v1(24.13,9.45) 20.29,9.45 17.98,11.76 10.13,11.76 8.4,10.02 8.4,8.14 7.24,6.99 3.1,6.99 1.2,5.08 D5.2
  BOTTOM w0.127: Q1.3 24.17,9.41 v1(24.13,9.45)
N581567: length 1.5
  BOTTOM w0.508: U2.5 9.72,7.43 9.78,7.49 R2.1
N582068: length 23.7
  TOP w0.127: v1(3.61,13.49) 4.57,12.52 4.57,8.28 3.86,7.57 v1(3.07,7.57) ; D1.2 v1(0.6,26.31)
  BOTTOM w0.127: v1(3.61,13.49) 3.61,14.59 3.07,15.13 3.07,20.83 3.07,21.43 3.43,21.79 3.43,23.04 3,23.47 2.57,23.47 1.24,24.79 1.24,25.67 v1(0.6,26.31) ; R1.1 3.15,7.49 v1(3.07,7.57)
N712650: length 34.6
  TOP w0.127: v1(26.01,9.4) 25.66,9.05 20.21,9.05 17.73,11.53 10.34,11.53 8.81,10.01 8.81,8.03 6.88,6.1 6.88,2.82 5.23,1.17 2.11,1.17 1.88,1.4 D6.2
  BOTTOM w0.127: Q2.3 26.02,9.41 v1(26.01,9.4)
N784297: length 3.5
  BOTTOM w0.254: U3.3 10.42,17.66 10.1,17.34 R16.2
  BOTTOM w0.381: R19.1 C13.1 10.03,16.36 10.1,16.42 R16.2
N789136: length 1
  BOTTOM w0.381: R19.2 9.02,13.91 R18.1
N816306: length 2.1
  TOP w0.127: R22.1 8.86,19.75 8.48,19.36 8.18,19.36 7.77,18.94 J1.A5
N816310: length 1.9
  TOP w0.127: J1.B5 4.99,17.69 v1(4.83,17.53)
  BOTTOM w0.127: v1(4.83,17.53) 4.79,17.49 R15.1
N918116: length 1.6
  BOTTOM w0.254: U6.B2 18.55,16.03 18.48,15.96 R23.2
N5338470: length 8.3
  TOP w0.127: v1(0.89,3.69) 0.6,3.4 D6.1
  BOTTOM w0.127: v1(0.89,3.69) 0.89,6.99 2.87,8.97 3.59,8.97 4,9.37 R6.1
N5774440: length 4.6
  TOP w0.127: v1(1.65,6.6) 1.23,6.6 1.23,6.6 D5.1
  BOTTOM w0.127: v1(1.65,6.6) 1.65,7.24 2.92,8.51 R5.1
N5815470: length 1.3
  BOTTOM w0.381: U2.1 6.14,7.49 R1.2

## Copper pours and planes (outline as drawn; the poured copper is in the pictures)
3V3 on BOTTOM: 11.18,13.21 15.11,13.21 15.75,13.84 15.75,17.14 16,17.4 18.54,17.4 18.67,17.53 18.67,17.91 18.29,18.29 15.24,18.29 14.61,17.65 14.61,14.99 14.22,14.61 11.18,14.61
GND on TOP: -1.65,-1.02 -1.65,30.61 -1.4,30.86 15.37,30.86 15.88,30.35 15.88,11.56 48.51,11.56 48.51,12.83 49.02,12.83 49.02,18.67 50.29,19.94 52.07,19.94 53.98,21.84 53.85,21.97 53.85,30.1 55.37,31.62 59.44,31.62 61.34,29.72 61.34,-1.02 ; 8 cut-outs
GND on BOTTOM: -1.52,30.61 -1.52,-0.38 60.96,-0.38 60.96,30.61 ; 28 cut-outs
GND on GND: -0.89,30.73 -0.89,-0.89 61.47,-0.89 61.47,30.73
GND on POWER: -0.38,30.35 -0.38,-0.89 62.87,-0.89 62.87,30.35 ; 7 cut-outs
VBAT on BOTTOM: 12.93,21.31 14.17,21.31 14.25,21.39 14.25,22.61 14.1,22.76 12.8,22.76 12.78,22.73 9.91,22.73 9.78,22.61 9.78,21.97 9.91,21.84 12.4,21.84
VBAT on POWER: 8.13,26.42 9.14,26.42 11.3,24.26 11.3,22.1 11.18,21.97 9.91,21.97 9.78,22.1 9.78,22.48 7.87,24.38 7.87,26.16
VBUS_D on BOTTOM: 18.54,12.7 18.54,9.27 15.49,9.27 15.49,12.83 16.26,13.59 17.65,13.59
VCC on BOTTOM: 18.19,20.7 18.92,20.7 19.05,20.57 19.05,19.94 18.67,19.56 16.38,19.56 15.88,19.05 12.19,19.05 11.94,19.3 11.94,19.56 11.68,19.81 11.3,19.81 11.3,21.46 11.43,21.59 12.06,21.59 12.83,20.83 18.06,20.83
VDD on POWER: 21.59,23.5 20.7,24.38 20.7,25.78 21.21,26.29 23.24,26.29 24.26,25.27 32.89,25.27 33.4,24.77 33.4,22.99 33.02,22.61 27.3,22.61 26.42,23.5
VDD on POWER: 34.42,21.84 34.42,17.27 37.72,13.97 40.01,13.97 40.13,14.1 40.13,14.86 37.72,17.27 37.72,18.29 37.85,18.41 38.48,18.41 38.99,17.91 39.37,17.91 39.62,18.16 39.62,19.81 39.12,20.32 36.96,20.32 35.31,21.97 34.54,21.97
GREEN_POWER on BOTTOM: 12.57,10.54 13.72,10.54 13.84,10.41 13.84,8.13 13.72,8 12.7,8 12.45,8.26 12.45,10.41
Net_24 on TOP (solid shape): outline of 388 points within 0.5,-7.5 122.5,-3.5
Net_24 on TOP (solid shape): outline of 388 points within 0.5,99.5 122.5,103.5
Net_24 on BOTTOM (solid shape): outline of 388 points within 0.5,-7.5 122.5,-3.5
Net_24 on BOTTOM (solid shape): outline of 388 points within 0.5,99.5 122.5,103.5
N724860 on BOTTOM: 10.79,18.29 10.79,16.26 11.18,15.88 13.72,15.88 13.72,17.27 11.56,17.27 11.05,17.78 11.05,18.29

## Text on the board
Ref Des/Silkscreen Bottom: BOOT0 | VDD | GND | TX1 | SLOT C | SCL | RX1 | SDA | AIN1 | IO1 | IO2 | BAT | SLOT D
